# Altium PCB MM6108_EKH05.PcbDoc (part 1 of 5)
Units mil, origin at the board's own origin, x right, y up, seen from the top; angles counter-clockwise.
Board outline 6023.62 x 3425.2 mil, 4 copper layers (Top Layer, Ground Plane, Middle Layer, Bottom Layer), stack 76.15 mil thick; 212 components, 163 nets, 749 pads, 1477 vias.
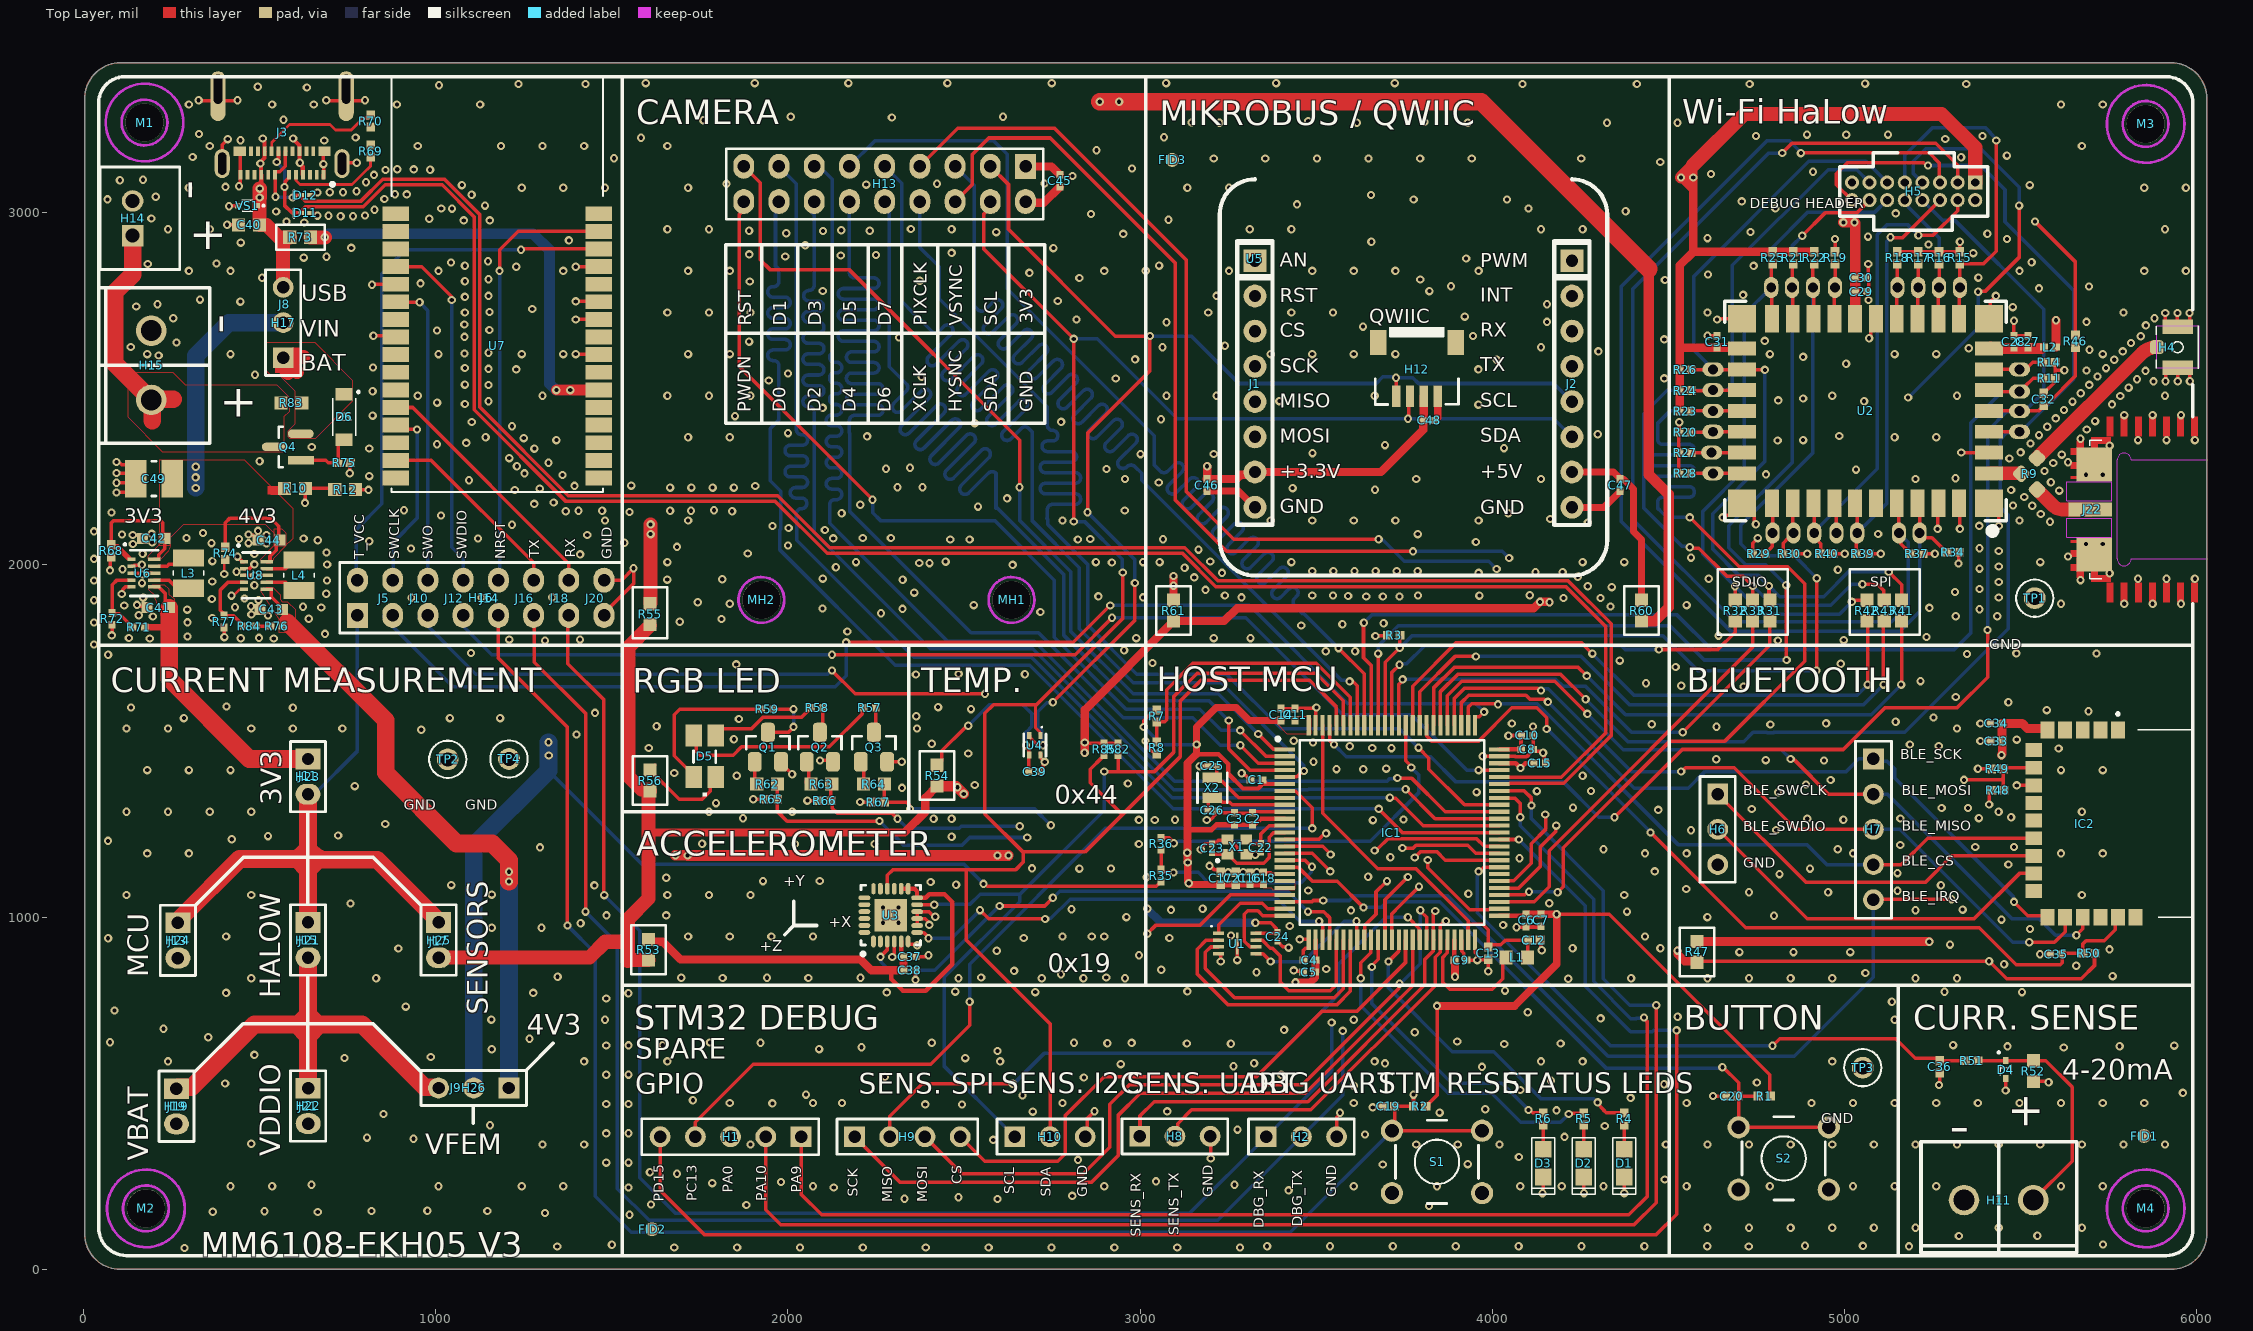
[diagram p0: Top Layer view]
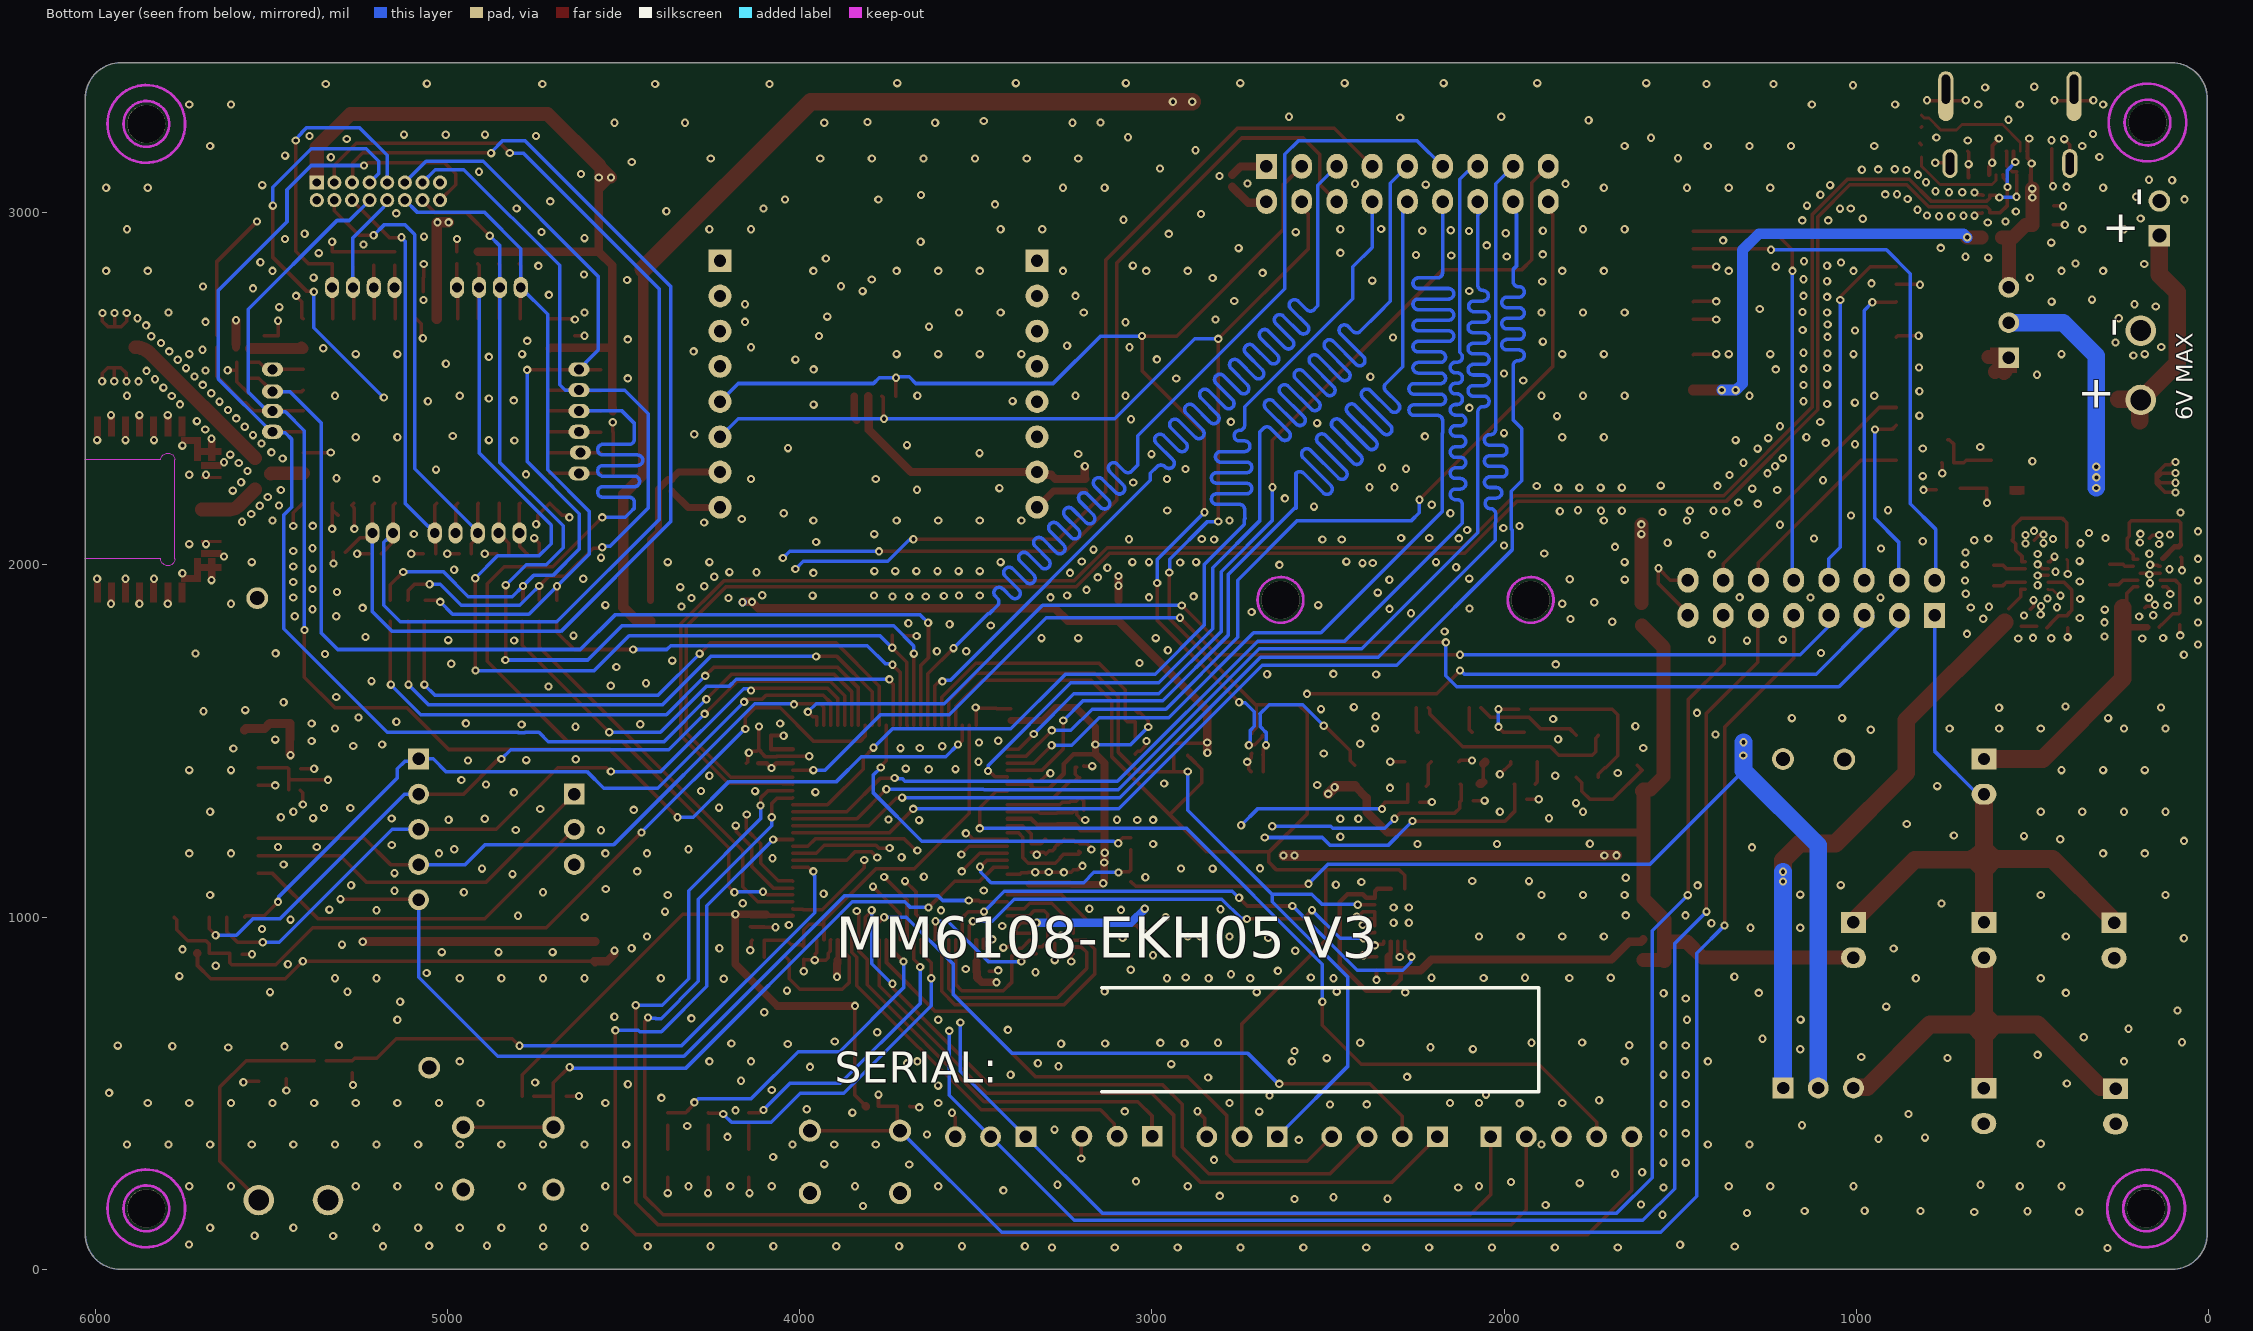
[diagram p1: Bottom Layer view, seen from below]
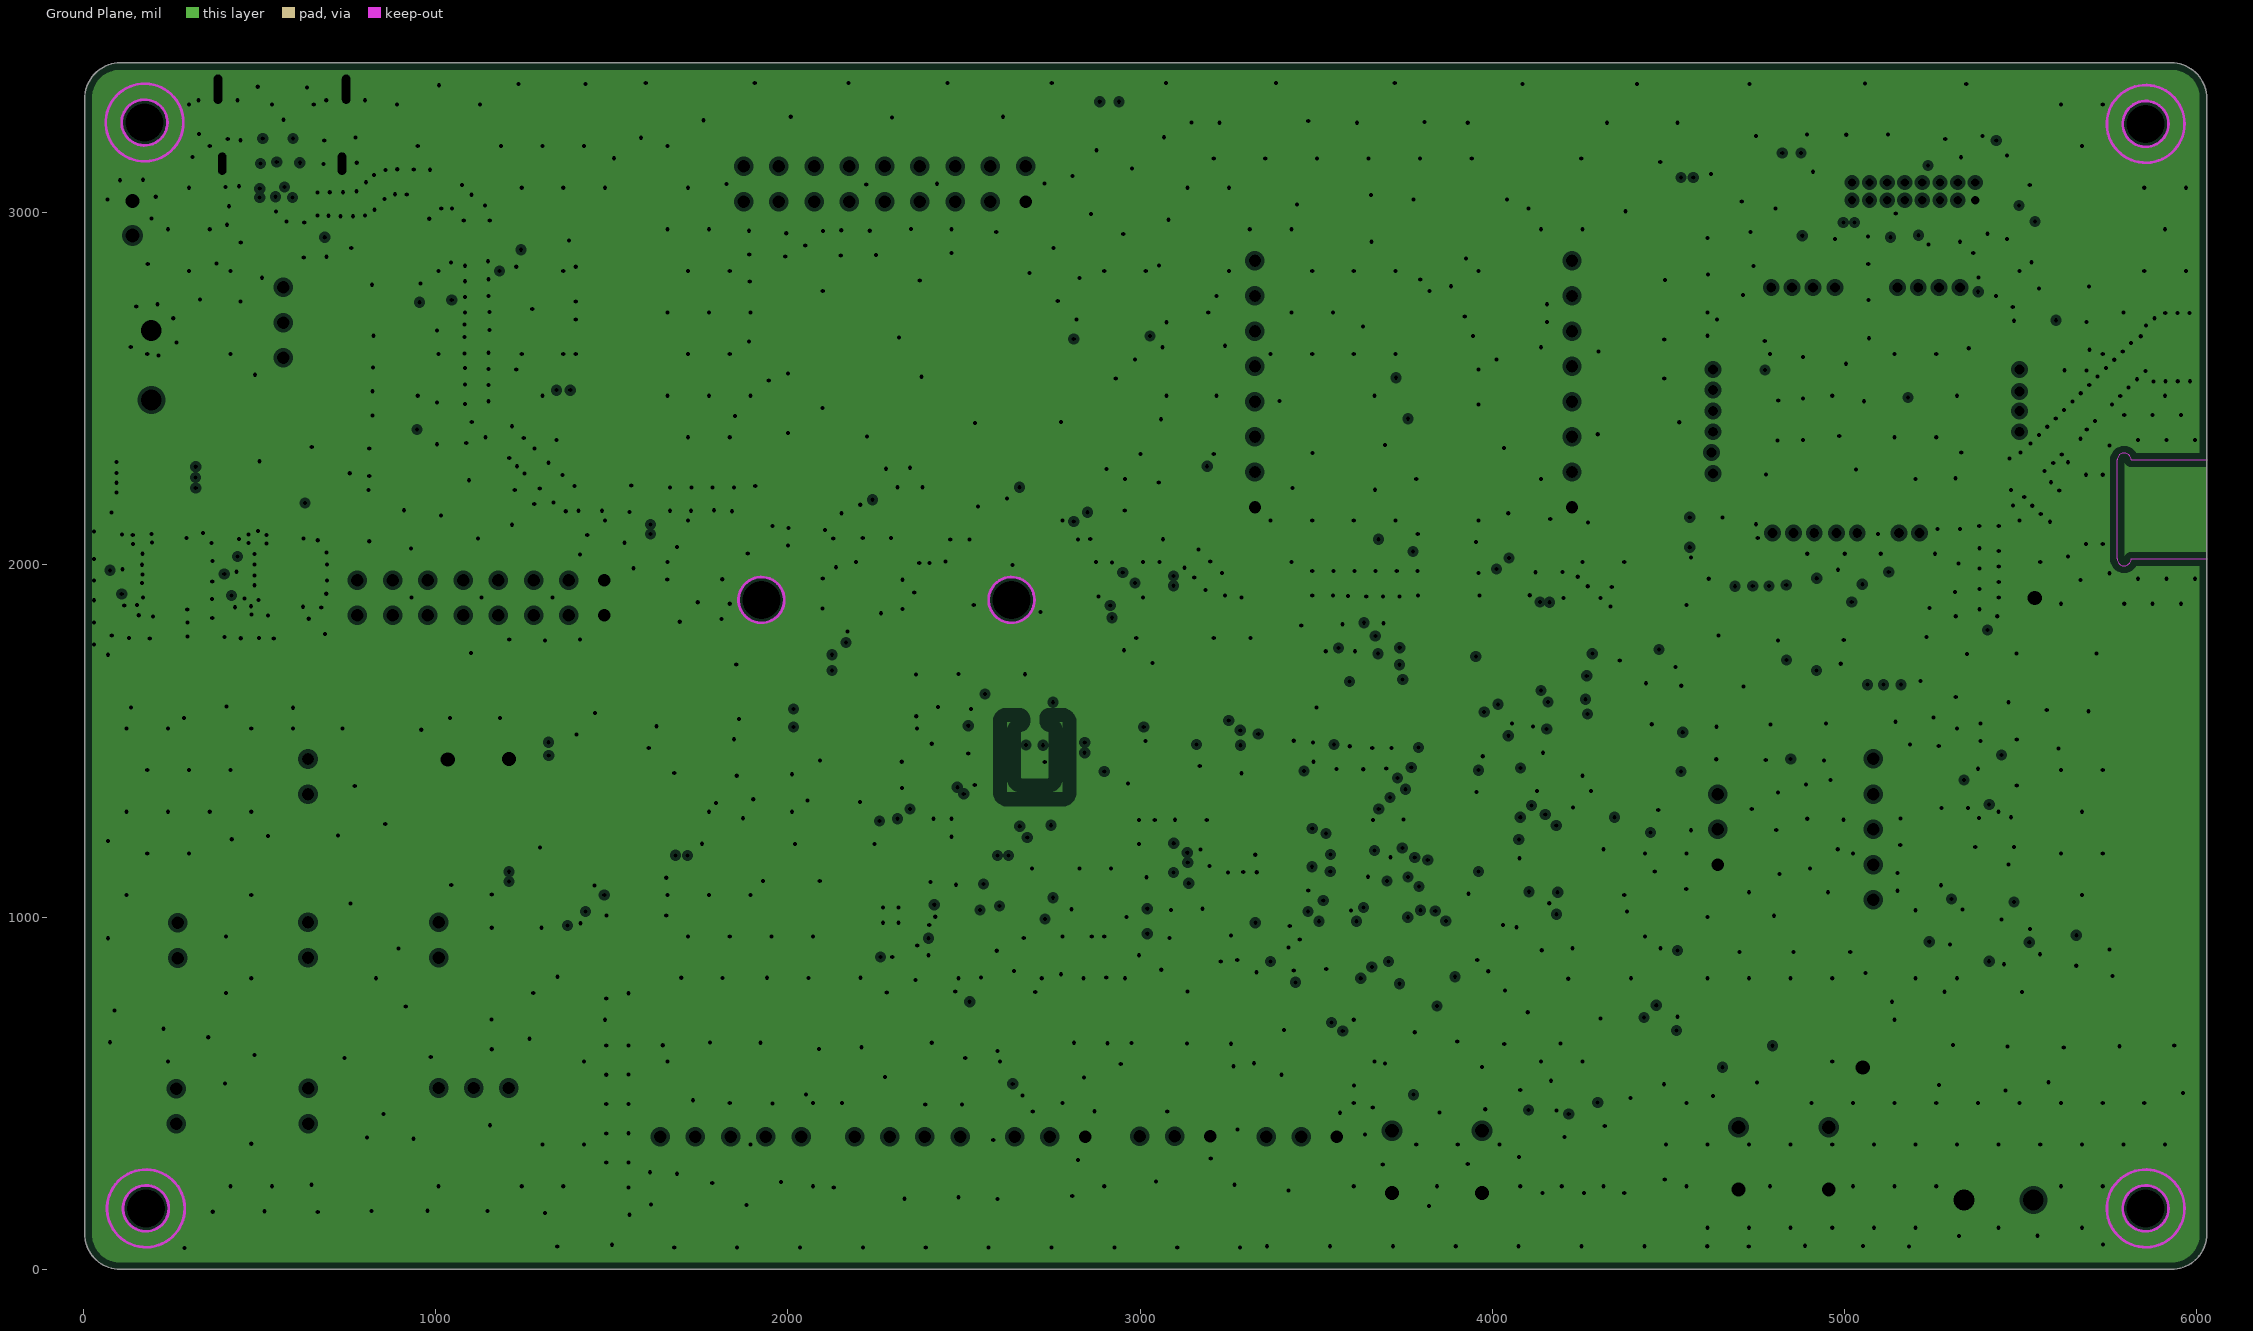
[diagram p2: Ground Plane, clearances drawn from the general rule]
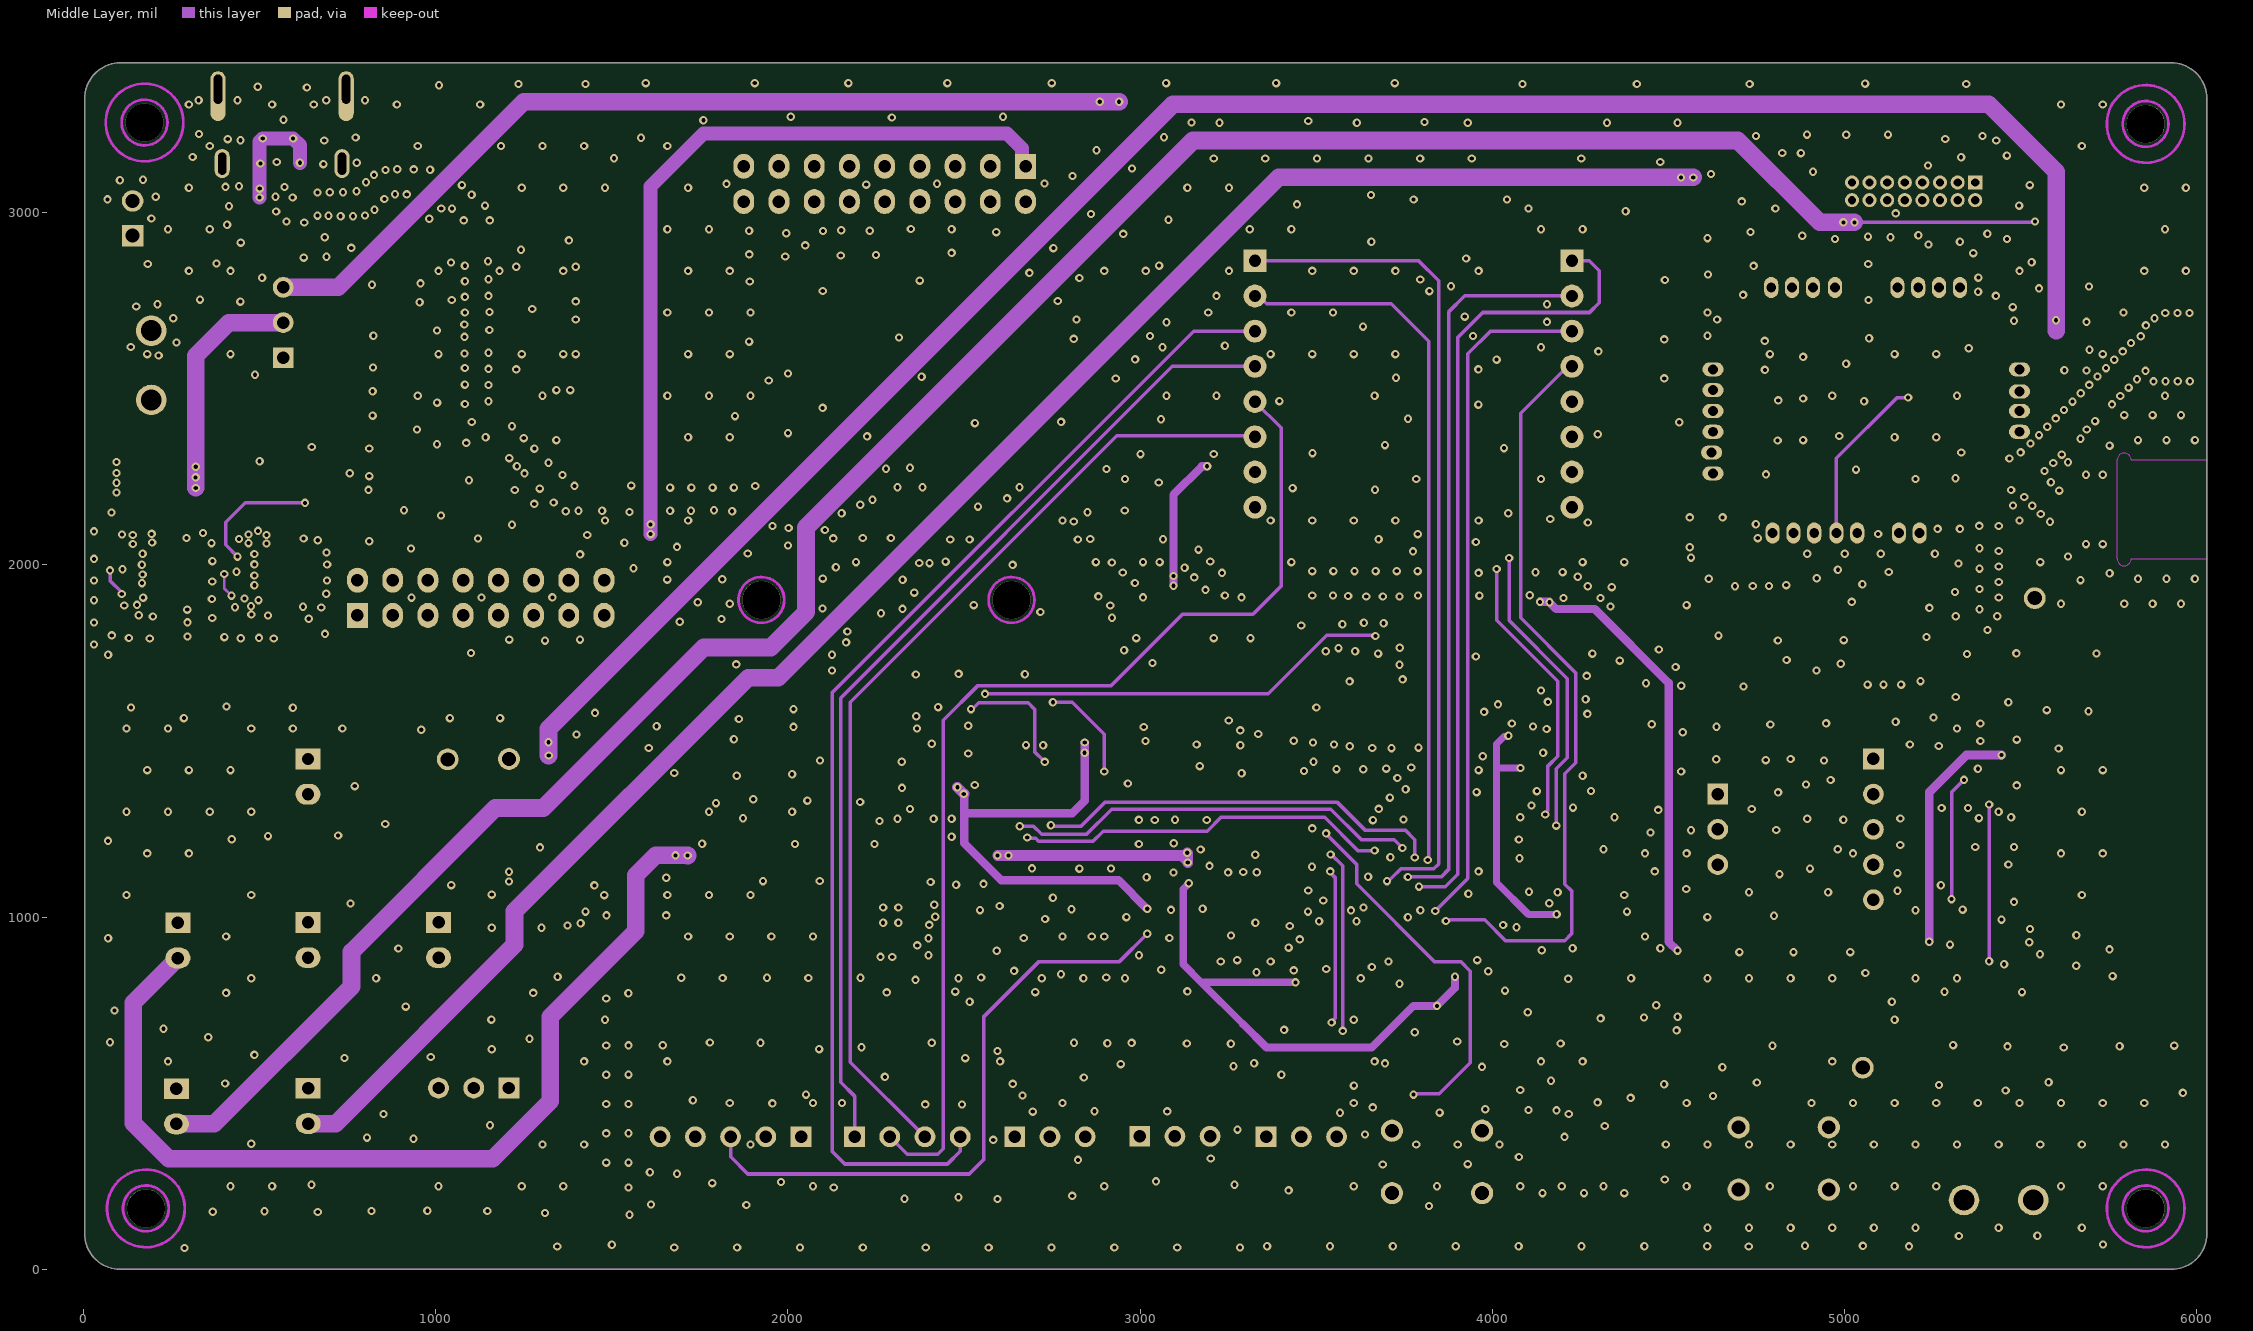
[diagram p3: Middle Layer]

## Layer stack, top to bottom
Top Solder: solder mask 0.8, SM-001, Dk 3.8
Top Layer: signal copper 1.4
Dielectric 2: prepreg 13.2, PP-006, Dk 4.11
Ground Plane: plane copper 1.25, net GND
Dielectric 1: prepreg 44.5, Core, Dk 4
Middle Layer: signal copper 1.25
Dielectric 5: prepreg 13.15, PP-006, Dk 4.11
Bottom Layer: signal copper 1.4
Bottom Solder: solder mask 0.8, SM-001, Dk 3.8

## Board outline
3.94,3188.98 3.94,3325.2 cw(c103.94,3325.2) 103.94,3425.2 5927.56,3425.2 cw(c5927.56,3325.2) 6027.56,3325.2 6027.56,100 cw(c5927.56,100) 5927.56,0 103.94,0 cw(c103.94,100) 3.94,100 3.94,275.59

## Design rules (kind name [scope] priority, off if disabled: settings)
AssemblyTestPointUsage [All] p0: scope1count=1 scope1_0_kind=Board scope1_0_value=Board scope2count=1 scope2_0_kind=Board scope2_0_value=Board commentlength=0
AssemblyTestPointUsage [All] p1: allowmultiple=TRUE
AssemblyTestpoint [All] p0: scope1count=1 scope1_0_kind=Board scope1_0_value=Board scope2count=1 scope2_0_kind=Board scope2_0_value=Board commentlength=0
AssemblyTestpoint [All] p1: testpointundercomponent=TRUE minsize=40 maxsize=100 preferedsize=60 minholesize=0 maxholesize=40 preferedholesize=32 testpointgrid=1 usegrid=FALSE gridtolerance=0.01 allowsidetop=TRUE
BoardOutlineClearance [All] p0 off: scope1count=1 scope1_0_kind=Board scope1_0_value=Board scope2count=1 scope2_0_kind=Board scope2_0_value=Board commentlength=140 gap=12 // Protel DXP Scope 1 Expression Was: (not OnTopSilkscreen) AND (NOT OnBottomSilkscreen) and (not OnMultiLayer) and (not InComponent('H3'))
BoardOutlineClearance [(not OnTopSilkscreen) AND (NOT OnBottomSilkscreen) and (not OnMultiLayer) and (not InComponent('H3'))] p1: gap=12 ignorepadtopadclearanceinfootprint=FALSE
Clearance Clearance_SMA [All] p0: scope1count=1 scope1_0_kind=Component scope1_0_value=J22 scope2count=1 scope2_0_kind=Component scope2_0_value=J22 commentlength=0 gap=0.01
Clearance Clearance_1 [All] p0: scope1count=1 scope1_0_kind=Board scope1_0_value=Board scope2count=1 scope2_0_kind=Board scope2_0_value=Board commentlength=0 gap=6
Clearance Clearance_USB [All] p0 off: scope1count=1 scope1_0_kind=Board scope1_0_value=Board scope2count=1 scope2_0_kind=Board scope2_0_value=Board commentlength=65 gap=6 // Protel DXP Scope 1 Expression Was: InDifferentialPair('USBC')
Clearance Clearance_RF [All] p0: scope1count=1 scope1_0_kind=NetClass scope1_0_value="50 Ohms" scope2count=1 scope2_0_kind=Board scope2_0_value=Board commentlength=0 gap=8.8
Clearance Clearance_RF_Poly [All] p0 off: scope1count=1 scope1_0_kind=Board scope1_0_value=Board scope2count=1 scope2_0_kind=NetClass scope2_0_value=RF-Net commentlength=50 gap=7.87 // Protel DXP Scope 1 Expression Was: (InPolygon)
Clearance Clearance_SMA [InComponent('J22') vs InComponent('J22')] p1: gap=0.01 ignorepadtopadclearanceinfootprint=TRUE
Clearance Clearance_RF_Poly [(InPolygon) vs InNetClass('RF-Net')] p2: gap=7.87 ignorepadtopadclearanceinfootprint=TRUE
Clearance Clearance_RF [InNetClass('50 Ohms')] p3: gap=8.8 ignorepadtopadclearanceinfootprint=TRUE except(3.94: Arc-Arc Arc-Track Track-Track)
Clearance Clearance_USB [InDifferentialPair('USBC')] p4: gap=6 ignorepadtopadclearanceinfootprint=TRUE
Clearance Clearance_1 [All] p5: gap=6 ignorepadtopadclearanceinfootprint=TRUE
ComponentClearance [All] p0: scope1count=1 scope1_0_kind=Board scope1_0_value=Board scope2count=1 scope2_0_kind=Board scope2_0_value=Board commentlength=0 gap=10 collisioncheckmode=3
DiffPairsRouting DiffPairsRouting_USBC [All] p0 off: scope1count=1 scope1_0_kind=Board scope1_0_value=Board scope2count=1 scope2_0_kind=Board scope2_0_value=Board commentlength=65 // Protel DXP Scope 1 Expression Was: InDifferentialPair('USBC')
DiffPairsRouting DiffPairsRouting_USBC [InDifferentialPair('USBC')] p1 off: maxlimit=10 minlimit=5 mostfreqgap=10 toplayer_maxgap=6 toplayer_prefgap=6 toplayer_minwidth=7.75 toplayer_maxwidth=11 toplayer_prefwidth=10 impedanceprofiledriven=TRUE impedanceprofileid={FA8D62EB-FDD2-4305-96CF-BF7F0CD6B75F} impedanceprofilevalue=90.000000 maxuncoupledlength=500
FabricationTestPointUsage [All] p0 off: scope1count=1 scope1_0_kind=Board scope1_0_value=Board scope2count=1 scope2_0_kind=Board scope2_0_value=Board commentlength=0 valid=0 allowmultiple=FALSE
FabricationTestPointUsage [All] p1 off: valid=0 allowmultiple=FALSE
FabricationTestpoint [All] p0 off: scope1count=1 scope1_0_kind=Board scope1_0_value=Board scope2count=1 scope2_0_kind=Board scope2_0_value=Board commentlength=63 side=1 testpointundercomponent=TRUE minsize=40 maxsize=100 preferedsize=60 minholesize=0 maxholesize=40 preferedholesize=32 testpointgrid=1 // Protel DXP Scope 1 Expression Was: (IsPad And OnMultiLayer)
FabricationTestpoint [(IsPad And OnMultiLayer)] p1 off: side=1 testpointundercomponent=TRUE minsize=40 maxsize=100 preferedsize=60 minholesize=0 maxholesize=40 preferedholesize=32 testpointgrid=1 allowsidetop=TRUE usegrid=TRUE gridtolerance=0.01
FanoutControl Fanout_Default [All] p0 off: scope1count=1 scope1_0_kind=Board scope1_0_value=Board scope2count=1 scope2_0_kind=Board scope2_0_value=Board commentlength=30 // Fanout_Default (Default Rule)
FanoutControl Fanout_Small [All] p0 off: scope1count=1 scope1_0_kind=Board scope1_0_value=Board scope2count=1 scope2_0_kind=Board scope2_0_value=Board commentlength=84 // Protel DXP Scope 1 Expression Was: (CompPinCount < 5)   Fanout_Small (Default Rule)
FanoutControl Fanout_SOIC [All] p0 off: scope1count=1 scope1_0_kind=Board scope1_0_value=Board scope2count=1 scope2_0_kind=Board scope2_0_value=Board commentlength=71 // Protel DXP Scope 1 Expression Was: IsSOIC   Fanout_SOIC (Default Rule)
FanoutControl Fanout_LCC [All] p0 off: scope1count=1 scope1_0_kind=Board scope1_0_value=Board scope2count=1 scope2_0_kind=Board scope2_0_value=Board commentlength=69 // Protel DXP Scope 1 Expression Was: IsLCC   Fanout_LCC (Default Rule)
FanoutControl Fanout_BGA [All] p0 off: scope1count=1 scope1_0_kind=Board scope1_0_value=Board scope2count=1 scope2_0_kind=Board scope2_0_value=Board commentlength=69 // Protel DXP Scope 1 Expression Was: IsBGA   Fanout_BGA (Default Rule)
FanoutControl Fanout_BGA [IsBGA] p1 off: bgadir=Out bgaviamode=Centered fanoutstyle=Auto fanoutdirection=Alternating viagrid=1 // Fanout_BGA (Default Rule)
FanoutControl Fanout_LCC [IsLCC] p2 off: bgadir=Out bgaviamode=Centered fanoutstyle=Auto fanoutdirection=Alternating viagrid=1 // Fanout_LCC (Default Rule)
FanoutControl Fanout_SOIC [IsSOIC] p3 off: bgadir=Out bgaviamode=Centered fanoutstyle=Auto fanoutdirection=Alternating viagrid=1 // Fanout_SOIC (Default Rule)
FanoutControl Fanout_Small [(CompPinCount < 5)] p4 off: bgadir=Out bgaviamode=Centered fanoutstyle=Auto fanoutdirection=OutThenIn viagrid=1 // Fanout_Small (Default Rule)
FanoutControl Fanout_Default [All] p5 off: bgadir=Out bgaviamode=Centered fanoutstyle=Auto fanoutdirection=Alternating viagrid=1 // Fanout_Default (Default Rule)
Height [All] p0 off: scope1count=1 scope1_0_kind=Board scope1_0_value=Board scope2count=1 scope2_0_kind=Board scope2_0_value=Board commentlength=0
Height "Under Socket" [All] p0 off: scope1count=1 scope1_0_kind=Board scope1_0_value=Board scope2count=1 scope2_0_kind=Board scope2_0_value=Board commentlength=64 // Protel DXP Scope 1 Expression Was: WithinRoom('ROOM_SOCKET')
Height "POGO Pins" [All] p0: scope1count=1 scope1_0_kind=ComponentClass scope1_0_value=POGO scope2count=1 scope2_0_kind=Board scope2_0_value=Board commentlength=0
Height TP1 [All] p0: scope1count=1 scope1_0_kind=Component scope1_0_value=TP1 scope2count=1 scope2_0_kind=Board scope2_0_value=Board commentlength=0
Height TP1 [InComponent('TP1')] p1: minheight=0 maxheight=472.44 prefheight=118.11
Height "POGO Pins" [InComponentClass('POGO')] p2: minheight=0 maxheight=275.59 prefheight=196.85
Height "Under Socket" [WithinRoom('ROOM_SOCKET')] p3: minheight=0 maxheight=157.48 prefheight=118.11
Height [All] p4 off: minheight=0 maxheight=1000 prefheight=500
HoleSize [All] p0: scope1count=1 scope1_0_kind=Board scope1_0_value=Board scope2count=1 scope2_0_kind=Board scope2_0_value=Board commentlength=0 absolutevalues=TRUE maxlimit=200 minlimit=6 maxpercent=80.000 minpercent=20.000
HoleSize [All] p1: absolutevalues=TRUE maxlimit=200 minlimit=6 maxpercent=80.000 minpercent=20.000
HoleToHoleClearance [All] p0: scope1count=1 scope1_0_kind=Board scope1_0_value=Board scope2count=1 scope2_0_kind=Board scope2_0_value=Board commentlength=0
HoleToHoleClearance [All] p1: gap=8 allowstackedmicrovias=TRUE
LayerPairs [All] p0 off: scope1count=1 scope1_0_kind=Board scope1_0_value=Board scope2count=1 scope2_0_kind=Board scope2_0_value=Board commentlength=0 enforce=TRUE
LayerPairs [All] p1 off: enforce=TRUE
MatchedLengths SDIO_2 [All] p0: scope1count=1 scope1_0_kind=NetClass scope1_0_value=SDIO_2 scope2count=1 scope2_0_kind=Board scope2_0_value=Board commentlength=0 tolerance=2000 amplitude=200 gap=20 style=90-Degree
MatchedLengths DCMI [All] p0: scope1count=1 scope1_0_kind=NetClass scope1_0_value=DCMI scope2count=1 scope2_0_kind=Board scope2_0_value=Board commentlength=0 tolerance=1000 amplitude=200 gap=20 style=90-Degree
MatchedLengths SDIO [All] p0: scope1count=1 scope1_0_kind=NetClass scope1_0_value=SDIO scope2count=1 scope2_0_kind=Board scope2_0_value=Board commentlength=0 tolerance=2000 amplitude=200 gap=20 style=90-Degree
MatchedLengths MatchLengths_U1_Passives_J5 [All] p0 off: scope1count=1 scope1_0_kind=Board scope1_0_value=Board scope2count=1 scope2_0_kind=Board scope2_0_value=Board commentlength=98 tolerance=50 amplitude=200 gap=20 style=90-Degree // Protel DXP Scope 1 Expression Was: InxSignalClass('xSignals_U1_Passives_J5_MatchLengthsClass')
MatchedLengths MatchLengths_U1_Passives_J5_1 [All] p0 off: scope1count=1 scope1_0_kind=Board scope1_0_value=Board scope2count=1 scope2_0_kind=Board scope2_0_value=Board commentlength=100 tolerance=50 amplitude=200 gap=20 style=90-Degree // Protel DXP Scope 1 Expression Was: InxSignalClass('xSignals_U1_Passives_J5_MatchLengthsClass_1')
MatchedLengths DCMI [InNetClass('DCMI')] p1: tolerance=1000 checknetsindiffpair=FALSE checkdiffpairvsdiffpair=TRUE checkxsignals=TRUE checkothers=TRUE
MatchedLengths SDIO [InNetClass('SDIO')] p2: tolerance=2000 checknetsindiffpair=FALSE checkdiffpairvsdiffpair=TRUE checkxsignals=TRUE checkothers=TRUE
MatchedLengths SDIO_2 [InNetClass('SDIO_2')] p3: tolerance=2000 checknetsindiffpair=FALSE checkdiffpairvsdiffpair=TRUE checkxsignals=TRUE checkothers=TRUE
MatchedLengths MatchLengths_U1_Passives_J5_1 [InxSignalClass('xSignals_U1_Passives_J5_MatchLengthsClass_1')] p4: tolerance=50 checknetsindiffpair=FALSE checkdiffpairvsdiffpair=TRUE checkxsignals=TRUE checkothers=TRUE
MatchedLengths MatchLengths_U1_Passives_J5 [InxSignalClass('xSignals_U1_Passives_J5_MatchLengthsClass')] p5: tolerance=50 checknetsindiffpair=FALSE checkdiffpairvsdiffpair=TRUE checkxsignals=TRUE checkothers=TRUE
MinimumSolderMaskSliver [All] p0 off: scope1count=1 scope1_0_kind=Board scope1_0_value=Board scope2count=1 scope2_0_kind=Board scope2_0_value=Board commentlength=96 // Protel DXP Scope 1 Expression Was: not InComponent('U4','U1','U5','U6','U7','U8','U9','U10')
MinimumSolderMaskSliver [not InComponent('U4','U1','U5','U6','U7','U8','U9','U10')] p1: minsoldermaskwidth=1
NetAntennae [All] p0: scope1count=1 scope1_0_kind=Board scope1_0_value=Board scope2count=1 scope2_0_kind=Board scope2_0_value=Board commentlength=0
PasteMaskExpansion [All] p0: scope1count=1 scope1_0_kind=Board scope1_0_value=Board scope2count=1 scope2_0_kind=Board scope2_0_value=Board commentlength=0 expansion=0
PlaneClearance [All] p0: scope1count=1 scope1_0_kind=Board scope1_0_value=Board scope2count=1 scope2_0_kind=Board scope2_0_value=Board commentlength=0 clearance=10
PlaneClearance [All] p1: clearance=10
PlaneConnect [All] p0: scope1count=1 scope1_0_kind=Board scope1_0_value=Board scope2count=1 scope2_0_kind=Board scope2_0_value=Board commentlength=0 planeconnectstyle=Relief reliefexpansion=20 reliefentries=4 reliefconductorwidth=10 reliefairgap=10
PlaneConnect PlaneConnect_1 [All] p0 off: scope1count=1 scope1_0_kind=Board scope1_0_value=Board scope2count=1 scope2_0_kind=Board scope2_0_value=Board commentlength=166 planeconnectstyle=Relief reliefexpansion=15.75 reliefentries=4 reliefconductorwidth=10 reliefairgap=7.87 // Protel DXP Scope 1 Expression Was: (InComponent('J5') OR InComponent('J6') OR InComponent('J13') OR InComponent('J11') OR InComponent('J12')) OR InComponent('H3')
PlaneConnect PlaneConnect_1 [(InComponent('J5') OR InComponent('J6') OR InComponent('J13') OR InComponent('J11') OR InComponent('J12')) OR InComponent('H3')] p1: planeconnectstyle=Relief reliefexpansion=15.75 reliefentries=4 reliefconductorwidth=10 reliefairgap=7.87
PlaneConnect [All] p2: pad.planeconnectstyle=Relief pad.reliefexpansion=20 pad.reliefentries=4 pad.reliefconductorwidth=10 pad.reliefairgap=10 via.planeconnectstyle=Direct via.reliefexpansion=20 via.reliefentries=4 via.reliefconductorwidth=10 via.reliefairgap=10
PolygonConnect [All] p0: scope1count=1 scope1_0_kind=Board scope1_0_value=Board scope2count=1 scope2_0_kind=Board scope2_0_value=Board commentlength=0 connectstyle=Relief reliefconductorwidth=10 reliefentries=4 polygonreliefangle="90 Angle"
PolygonConnect PolygonConnect_1 [All] p0 off: scope1count=1 scope1_0_kind=Net scope1_0_value=GND scope2count=1 scope2_0_kind=Board scope2_0_value=Board commentlength=145 connectstyle=Relief reliefconductorwidth=10 reliefentries=4 polygonreliefangle="90 Angle" // Protel DXP Scope 2 Expression Was: (InComponent('J5') OR InComponent('J6') OR InComponent('J13') OR InComponent('J11') OR InComponent('J12'))
PolygonConnect PolygonConnect_1 [InNet('GND') vs (InComponent('J5') OR InComponent('J6') OR InComponent('J13') OR InComponent('J11') OR InComponent('J12'))] p1: connectstyle=Relief reliefconductorwidth=10 reliefentries=4 polygonreliefangle="90 Angle" airgapwidth=7.87
PolygonConnect [All] p2: thpad.connectstyle=Relief thpad.reliefconductorwidth=10 thpad.reliefentries=4 thpad.polygonreliefangle="90 Angle" thpad.airgapwidth=10 smdpad.connectstyle=Direct smdpad.reliefconductorwidth=10 smdpad.reliefentries=4 smdpad.polygonreliefangle="90 Angle" smdpad.airgapwidth=10 via.connectstyle=Direct via.reliefconductorwidth=10 via.reliefentries=4 via.polygonreliefangle="90 Angle" via.airgapwidth=10
RoutingCorners [All] p0: scope1count=1 scope1_0_kind=Board scope1_0_value=Board scope2count=1 scope2_0_kind=Board scope2_0_value=Board commentlength=0 cornerstyle=45-Degree minsetback=100 maxsetback=100
RoutingLayers [All] p0: scope1count=1 scope1_0_kind=Board scope1_0_value=Board scope2count=1 scope2_0_kind=Board scope2_0_value=Board commentlength=0 top layer=Automatic mid layer 1=Automatic bottom layer=Automatic
RoutingPriority [All] p0: scope1count=1 scope1_0_kind=Board scope1_0_value=Board scope2count=1 scope2_0_kind=Board scope2_0_value=Board commentlength=0
RoutingTopology [All] p0: scope1count=1 scope1_0_kind=Board scope1_0_value=Board scope2count=1 scope2_0_kind=Board scope2_0_value=Board commentlength=0 topology=Shortest
RoutingVias [All] p0: scope1count=1 scope1_0_kind=Board scope1_0_value=Board scope2count=1 scope2_0_kind=Board scope2_0_value=Board commentlength=0 holewidth=11.81 width=23.62 viastyle="Through Hole" minholewidth=8 minwidth=19.68 maxholewidth=28 maxwidth=50
RoutingVias [All] p1: holewidth=11.81 width=23.62 viastyle="Through Hole" minholewidth=8 minwidth=19.68 maxholewidth=28 maxwidth=50
ShortCircuit [All] p0: scope1count=1 scope1_0_kind=Board scope1_0_value=Board scope2count=1 scope2_0_kind=Board scope2_0_value=Board commentlength=0 allowed=FALSE
SilkToBoardRegionClearance [All] p0: scope1count=1 scope1_0_kind=Board scope1_0_value=Board scope2count=1 scope2_0_kind=Board scope2_0_value=Board commentlength=0
SilkToSilkClearance [All] p0: scope1count=1 scope1_0_kind=Board scope1_0_value=Board scope2count=1 scope2_0_kind=Board scope2_0_value=Board commentlength=0
SilkToSilkClearance [All] p1: silktosilkclearance=8
SilkToSolderMaskClearance [All] p0 off: scope1count=1 scope1_0_kind=Board scope1_0_value=Board scope2count=1 scope2_0_kind=Board scope2_0_value=Board commentlength=44 // Protel DXP Scope 1 Expression Was: IsPad
SilkToSolderMaskClearance [IsPad] p1: minsilkscreentomaskgap=4 clearancetoexposedcopper=TRUE
SolderMaskExpansion [All] p0: scope1count=1 scope1_0_kind=Board scope1_0_value=Board scope2count=1 scope2_0_kind=Board scope2_0_value=Board commentlength=0 expansion=4
SolderMaskExpansion [All] p1: expansion=4 istentingtop=FALSE
SupplyNets [All] p0: scope1count=1 scope1_0_kind=Net scope1_0_value=GND scope2count=1 scope2_0_kind=Board scope2_0_value=Board commentlength=0 voltage=0.000
SupplyNets SupplyNets_7 [All] p0: scope1count=1 scope1_0_kind=Net scope1_0_value=VDD_PA scope2count=1 scope2_0_kind=Board scope2_0_value=Board commentlength=0 voltage=4.000
SupplyNets SupplyNets_6 [All] p0: scope1count=1 scope1_0_kind=Net scope1_0_value=VDD_LNA scope2count=1 scope2_0_kind=Board scope2_0_value=Board commentlength=0 voltage=4.000
SupplyNets SupplyNets_5 [All] p0: scope1count=1 scope1_0_kind=Net scope1_0_value=VDD_FEM scope2count=1 scope2_0_kind=Board scope2_0_value=Board commentlength=0 voltage=4.000
SupplyNets SupplyNets_4 [All] p0: scope1count=1 scope1_0_kind=Net scope1_0_value=VDD5_RPi scope2count=1 scope2_0_kind=Board scope2_0_value=Board commentlength=0 voltage=5.000
SupplyNets SupplyNets_3 [All] p0: scope1count=1 scope1_0_kind=Net scope1_0_value=VDD5 scope2count=1 scope2_0_kind=Board scope2_0_value=Board commentlength=0 voltage=5.000
SupplyNets SupplyNets_2 [All] p0: scope1count=1 scope1_0_kind=Net scope1_0_value=VBAT scope2count=1 scope2_0_kind=Board scope2_0_value=Board commentlength=0 voltage=3.300
SupplyNets SupplyNets_1 [All] p0: scope1count=1 scope1_0_kind=Net scope1_0_value=VDD33 scope2count=1 scope2_0_kind=Board scope2_0_value=Board commentlength=0 voltage=3.300
SupplyNets SupplyNets_1 [InNet('VDD33')] p1: voltage=3.300
SupplyNets SupplyNets_2 [InNet('VBAT')] p2: voltage=3.300
SupplyNets SupplyNets_3 [InNet('VDD5')] p3: voltage=5.000
SupplyNets SupplyNets_4 [InNet('VDD5_RPi')] p4: voltage=5.000
SupplyNets SupplyNets_5 [InNet('VDD_FEM')] p5: voltage=4.000
SupplyNets SupplyNets_6 [InNet('VDD_LNA')] p6: voltage=4.000
SupplyNets SupplyNets_7 [InNet('VDD_PA')] p7: voltage=4.000
SupplyNets [InNet('GND')] p8: voltage=0.000
UnConnectedPin [All] p0 off: scope1count=1 scope1_0_kind=Board scope1_0_value=Board scope2count=1 scope2_0_kind=Board scope2_0_value=Board commentlength=0
UnConnectedPin [All] p1 off:
UnRoutedNet [All] p0: scope1count=1 scope1_0_kind=Board scope1_0_value=Board scope2count=1 scope2_0_kind=Board scope2_0_value=Board commentlength=0
UnRoutedNet [All] p1: checkbadconnections=TRUE
UnpouredPolygon [All] p0: scope1count=1 scope1_0_kind=Board scope1_0_value=Board scope2count=1 scope2_0_kind=Board scope2_0_value=Board commentlength=0
Width "RF Width_1" [All] p0 off: scope1count=1 scope1_0_kind=Board scope1_0_value=Board scope2count=1 scope2_0_kind=Board scope2_0_value=Board commentlength=65 maxlimit=23.62 minlimit=4.18 preferedwidth=10 // Protel DXP Scope 1 Expression Was: InDifferentialPair('USBC')
Width [All] p0: scope1count=1 scope1_0_kind=Board scope1_0_value=Board scope2count=1 scope2_0_kind=Board scope2_0_value=Board commentlength=0 maxlimit=50 minlimit=8 preferedwidth=8
Width "RF Width" [All] p0: scope1count=1 scope1_0_kind=NetClass scope1_0_value="50 OHMs" scope2count=1 scope2_0_kind=Board scope2_0_value=Board commentlength=0 maxlimit=39.37 minlimit=4.18 preferedwidth=10
Width "RF Width" [InNetClass('50 OHMs')] p1: maxlimit=39.37 minlimit=4.18 preferedwidth=10 toplayer_minwidth=12.51 toplayer_prefwidth=39 impedanceprofiledriven=TRUE impedanceprofileid={FF55CEB2-EE64-462C-BC0D-290E837BE369} impedanceprofilevalue=50.000000 minimp=50.000000 maximp=50.000000 favimp=50.000000
Width "RF Width_1" [InDifferentialPair('USBC')] p2: maxlimit=23.62 minlimit=4.18 preferedwidth=10 toplayer_minwidth=7 minimp=50.000000 maximp=50.000000 favimp=50.000000
Width [All] p3: maxlimit=50 minlimit=8 preferedwidth=8
10 further rules are at their usual default settings.

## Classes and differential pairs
component class U_Mechanical: FID1 FID2 FID3 J5 J8 J9 J10 J11 J12 J13 J14 J15 J16 J17 J18 J19 J20 J21 M1 M2 M3 M4 TP1 TP2 TP3 TP4
net class SDIO_2: SDMMC2_CLK SDMMC2_CMD SDMMC2_D0
net class DCMI: CAM_XCLK DCMI_D0 DCMI_D1 DCMI_D2 DCMI_D3 DCMI_D4 DCMI_D5 DCMI_D6 DCMI_D7 DCMI_HSYNC DCMI_PIXCLK DCMI_VSYNC
net class SDIO: MM_SDIO_CLK MM_SDIO_CMD MM_SDIO_D0 MM_SDIO_D1 MM_SDIO_D2 MM_SDIO_D3
net class "50 OHMs": ANT NetH4_1 NetJ22_1
component class U_Sensors: C36 C37 C38 C39 C45 C46 C47 C48 D4 D5 H8 H9 H10 H11 H12 H13 J1 J2 MH1 MH2 Q1 Q2 Q3 R51 R52 R53 R54 R55 R56 R57 R58 R59 R60 R61 R62 R63 R64 R65 R66 R67 U3 U4 U5
component class U_Power: C40 C41 C42 C43 C44 C49 D6 D11 D12 H14 H15 H16 H17 H19 H21 H22 H23 H24 H25 H26 J3 L3 L4 Q4 R10 R12 R35 R36 R68 R69 R70 R71 R72 R73 R74 R75 R76 R77 R83 R84 U6 U7 U8 VS1
component class U_BLE_Module: C33 C34 C35 H6 H7 IC2 R47 R48 R49 R50
component class U_STM_MCU: C1 C2 C3 C4 C5 C6 C7 C8 C9 C10 C11 C12 C13 C14 C15 C16 C17 C18 C19 C20 C21 C22 C23 C24 C25 C26 D1 D2 D3 H1 H2 IC1 L1 R1 R2 R3 R4 R5 R6 R7 R8 R82 R85 S1 S2 U1 X1 X2
component class U_HaLow_Module: C27 C28 C29 C30 C31 C32 H4 H5 J22 L2 R9 R11 R14 R15 R16 R17 R18 R19 R20 R21 R22 R23 R24 R25 R26 R27 R28 R29 R30 R31 R32 R33 R34 R37 R39 R40 R41 R42 R43 R46 U2
differential pair " ": +USBC_P -USBC_N

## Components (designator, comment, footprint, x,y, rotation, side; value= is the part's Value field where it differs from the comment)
C1 "GRM155R61A475MEAAD" 0402_cap 3330,1390 r0 top
C2 "C1005X7R1H104K050BE" 0402_cap 3318.9,1279.53 r270 top
C3 "CL05A106MP8NUB8" 0402_cap 3267.72,1279.53 r270 top
C4 "C1005X7R1H104K050BE" 0402_cap 3480.31,877.95 r0 top
C5 "CL05A106MP8NUB8" 0402_cap 3479.02,844.11 r0 top
C6 "C1005X7R1H104K050BE" 0402_cap 4095.37,990.6 r90 top
C7 "CL05A106MP8NUB8" 0402_cap 4137.08,991.19 r90 top
C8 "C1005X7R1H104K050BE" 0402_cap 4098.43,1476.38 r180 top
C9 "CL05A106MP8NUB8" 0402_cap 3909.45,877.95 r0 top
C10 "CL05A106MP8NUB8" 0402_cap 4098.43,1515.75 r180 top
C11 "C1005X7R1H104K050BE" 0402_cap 3440,1575 r270 top
C12 "GRM155R61E225ME15D" CAPC1005X06N 4117.13,935.04 r0 top
C13 "GRM155R61E225ME15D" CAPC1005X06N 3988.19,897.64 r270 top
C14 "CL05A106MP8NUB8" 0402_cap 3400,1575 r270 top
C15 "C1005X7R1H104K050BE" 0402_cap 4133.86,1437.01 r180 top
C16 "C1005X7R1H104K050BE" 0402_cap 3311.02,1110.24 r270 top
C17 "CL05A105KA5NQNC" CAPC1005X06N 3228.35,1110.24 r270 top
C18 "C1005X7R1H104K050BE" 0402_cap 3350.39,1110.24 r270 top
C19 "LMK105BJ104KV-F" CAPC1005X06N 3704.72,462.6 r180 top
C20 "LMK105BJ104KV-F" CAPC1005X06N 4679.13,492.13 r180 top
C21 "CL05A105KA5NQNC" CAPC1005X06N 3271.65,1110.24 r270 top
C22 "GRM0335C1E120JA01D" CAPC0603X03N 3342.52,1196.85 r270 top
C23 "GRM0335C1E120JA01D" CAPC0603X03N 3203.74,1195.87 r90 top
C24 "CL03A104KQ3NNNC" CAPC0603X03N 3389.76,944.88 r90 top
C25 "GRM0335C1E120JA01D" CAPC0603X03N 3204.72,1429.13 r0 top
C26 "GRM0335C1E120JA01D" CAPC0603X03N 3204.72,1303.15 r180 top
C27 "CL05A106MP8NUB8" 0402_cap 5519.69,2633.86 r90 top
C28 "C1005X7R1H104K050BE" 0402_cap 5480.31,2633.86 r90 top
C29 "C1005X7R1H104K050BE" 0402_cap 5046.18,2775.59 r0 top
C30 "CL05A106MP8NUB8" 0402_cap 5046.18,2814.96 r0 top
C31 "C1005X7R1H104K050BE" 0402_cap 4637.8,2633.86 r90 top
C32 "GRM155R61E225ME15D" CAPC1005X06N 5565,2470 r90 top
C33 "GRM155R61E225ME15D" CAPC1005X06N 5430,1500 r180 top
C34 "C1005X7R1H104K050BE" 0402_cap 5430,1550 r0 top
C35 "GRM155R71E103KA01D" 0402_cap 5600,895 r0 top
C36 "GRM155R71E103KA01D" CAPC1005X06N 5269.69,575.2 r270 top
C37 "C1005X7R1H104K050BE" 0402_cap 2345,888 r180 top
C38 "CL05A106MP8NUB8" 0402_cap 2345,849 r180 top
C39 "C1005X7R1H104K050BE" 0402_cap 2700.79,1413.39 r180 top
C40 "GRM188R61E106MA73J" CAPC1608X06N 470,2965 r180 top
C41 "GRM188R60J226MEA0D" 0603_cap 211.96,1878.74 r0 top
C42 "GRM188R60J106ME84D" 0603_cap 199.37,2075.12 r0 top
C43 "GRM188R60J226MEA0D" 0603_cap 533.15,1873.47 r0 top
C44 "GRM188R60J106ME84D" 0603_cap 526.34,2070.32 r0 top
C45 "C1005X7R1H104K050BE" 0402_cap 2771.65,3090.55 r90 top
C46 "C1005X7R1H104K050BE" 0402_cap 3188.98,2226.77 r90 top
C47 "C1005X7R1H104K050BE" 0402_cap 4362.2,2226.77 r90 top
C48 "C1005X7R1H104K050BE" 0402_cap 3820,2410 r180 top
C49 "CL32A107MPVNNNE" CAPC3225X20N 200,2245 r180 top
D1 "LTST-C170KRKT" LED_0805_RED 4374.02,301.57 r270 top
D2 "LTST-C170KGKT" LED_0805_GREEN 4258.86,301.57 r270 top
D3 "LTST-C170TBKT" LED_0805_BLUE 4143.7,301.57 r270 top
D4 "ESD8351XV2T1G" SOD-523-DIODE 5456.69,566.93 r270 top
D5 "150120M173000" WL-SFCW_1206 1763.78,1456.69 r90 top
D6 "MMSZ5231B7F" SOD-123FL 740,2420 r270 top
D11 "ESDALC6V1-1U2" 0201_DIODE 630,2999.22 r0 top
D12 "ESDALC6V1-1U2" 0201_DIODE 630,3050 r0 top
FID1 "PAD0002" FIDUCIAL_1MM 5849.65,378.7 r90 top
FID2 "PAD0002" FIDUCIAL_1MM 1614,114 r90 top
FID3 "PAD0002" FIDUCIAL_1MM 3090.55,3149.61 r90 top
H1 "2011-1X05G00SB" "HDR1X5 - Short Gold" 1887.01,376.69 r180 top
H2 "2011-1X03G00SB" HDR1X3 3457.38,376.69 r0 top
H4 "U.FL-R-SMT" U_FL-R-SMT 5944.88,2618.11 r270 top
H5 "FTSH-108-01-F-D-K" FTSH_108_D_K 5195.47,3060.43 r180 top
H6 "2011-1X03G00SB" HDR1X3 4639.37,1249.29 r270 top
H7 "2011-1X05G00SB" "HDR1X5 - Short Gold" 5081.42,1299.29 r270 top
H8 "2011-1X03G00SB" HDR1X3 3098.43,377.95 r0 top
H9 "2011-1X04G00SB" "HDR1X4 - Short Gold" 2338.88,376.69 r0 top
H10 "2011-1X03G00SB" HDR1X3 2743.7,376.69 r0 top
H11 "OSTTC020162" SCREW_TERM_2WAY_5MM 5338.58,196.85 r0 top
H12 "SM04B-SRSS-TBLFSN" SM04B-SRSS-TB 3785.59,2555.28 r90 top
H13 "PPTC092LFBN-RC" "HDR2X9 Female" 2674.41,3131.5 r180 top
H14 "B2B-XH-A" B2B-XH-A 160.12,2984.09 r90 top
H15 "OSTTC020162" SCREW_TERM_2WAY_5MM 192.6,2665.04 r270 top
H16 "2011-2X08TSB" "HDR2X8 Short Gold" 1077.76,1906.69 r0 top
H17 "2011-1X03G00SB" HDR1X3 566.93,2687.87 r90 top
H19 "2011-1X02G00SB-1" HDR1X2 264,463 r270 top
H21 "2011-1X02G00SB-1" HDR1X2 637.35,935 r270 top
H22 "2011-1X02G00SB-1" HDR1X2 638,464 r270 top
H23 "2011-1X02G00SB-1" HDR1X2 637.35,1399 r270 top
H24 "2011-1X02G00SB-1" HDR1X2 268,934 r270 top
H25 "2011-1X02G00SB-1" HDR1X2 1008,935 r270 top
H26 "2011-1X03G00SB" HDR1X3 1107.88,515 r180 top
IC1 "STM32U585VIT6Q" STM32U585VIT6 3714.57,1240.16 r0 top locked
IC2 "BLUENRG-M2SP" BLUENRGM2SP 5725.59,1265.75 r270 top
J1 "75915-308GLF" 75915-308LF 3325.59,2863.58 r0 top
J2 "75915-308GLF" 75915-308LF 4225.59,2863.58 r0 top
J3 "2012670005" USB-C_RCP 563.78,3228.94 r180 top locked
J5 "QPC02SXGN-RC" FP-QPC02SXGN-RC-MFG 852.76,1905.51 r90 top
J8 "QPC02SXGN-RC" FP-QPC02SXGN-RC-MFG 570,2740 r90 top
J9 "QPC02SXGN-RC" FP-QPC02SXGN-RC-MFG 1056.49,515 r180 top
J10 "QPC02SXGN-RC" FP-QPC02SXGN-RC-MFG 952.76,1905.51 r90 top
J11 "QPC02SXGN-RC" FP-QPC02SXGN-RC-MFG 638.16,1401.43 r90 top
J12 "QPC02SXGN-RC" FP-QPC02SXGN-RC-MFG 1052.76,1905.51 r90 top
J13 "QPC02SXGN-RC" FP-QPC02SXGN-RC-MFG 267.04,933.35 r90 top
J14 "QPC02SXGN-RC" FP-QPC02SXGN-RC-MFG 1152.76,1905.51 r90 top
J15 "QPC02SXGN-RC" FP-QPC02SXGN-RC-MFG 638.16,934.43 r90 top
J16 "QPC02SXGN-RC" FP-QPC02SXGN-RC-MFG 1252.76,1905.51 r90 top
J17 "QPC02SXGN-RC" FP-QPC02SXGN-RC-MFG 1009,932 r90 top
J18 "QPC02SXGN-RC" FP-QPC02SXGN-RC-MFG 1352.76,1905.51 r90 top
J19 "QPC02SXGN-RC" FP-QPC02SXGN-RC-MFG 265,463 r270 top
J20 "QPC02SXGN-RC" FP-QPC02SXGN-RC-MFG 1452.76,1905.51 r90 top
J21 "QPC02SXGN-RC" FP-QPC02SXGN-RC-MFG 638.16,462.78 r90 top
J22 "SM2924" SM2924-Footprint-1 5984.25,2157.48 r180 top
L1 "ASMPH-0603-2R2M-T" INDC1608X10N 4068.9,885.83 r180 top
L2 "BLM15PX600SN1D" 0402_ind 5582.68,2618.11 r0 top
L3 "DFE252012PR47MP2" INDC2520X120N 297.8,1976.69 r270 top
L4 "DFE252012PR47MP2" INDC2520X120N 611.55,1970.58 r270 top
M1 "MH_300_275_NPTH" MH_300_275_NPTH 173.23,3255.91 r0 top
M2 "MH_300_275_NPTH" MH_300_275_NPTH 177.17,173.23 r0 top
M3 "MH_300_275_NPTH" MH_300_275_NPTH 5854.33,3251.97 r0 top
M4 "MH_300_275_NPTH" MH_300_275_NPTH 5854.33,173.23 r0 top
MH1 "PAD0009" MH_300_275_NPTH 2634.57,1900.63 r0 top
MH2 "PAD0009" MH_300_275_NPTH 1924.57,1900.63 r0 top
Q1 "2N7002NXAKR" SOT95P240X120_GSD-3N(SOT23-3L) 1942.91,1484.25 r0 top
Q2 "2N7002NXAKR" SOT95P240X120_GSD-3N(SOT23-3L) 2090.54,1484.25 r0 top
Q3 "2N7002NXAKR" SOT95P240X120_GSD-3N(SOT23-3L) 2244.09,1484.25 r0 top
Q4 "IRLML6401TRPBF" FP-SOT23-IPC_A 580,2335 r180 top
R1 "MCR01MZPF1002" RESC1005X04N 4771.65,492.13 r180 top
R2 "MCR01MZPF1002" RESC1005X04N 3793.31,462.6 r180 top
R3 "ERJ-2RKF1001X" RESC1005X04N 3720,1800 r0 top
R4 "ERJ-2RKF1001X" RESC1005X04N 4374.02,427.16 r270 top
R5 "ERJ-2RKF1001X" RESC1005X04N 4258.86,427.16 r270 top
R6 "ERJ-2RKF1001X" RESC1005X04N 4143.7,427.16 r270 top
R7 "MCR01MZPF1002" RESC1005X04N 3047.24,1570.87 r90 top
R8 "MCR01MZPF1002" RESC1005X04N 3047.24,1480.31 r270 top
R9 "RES_AB" 0603_RES_AB_RA 5523.62,2236.22 r315 top
R10 "RC0603JR-070RL" RESC1608X06N 600.48,2217.17 r180 top
R11 "ERJ-2RKF1002X" RESC1005X04N 5580,2530 r180 top
R12 "RC0603JR-070RL" RESC1608X06N 743,2214 r0 top
R14 "ERJ-2RKF1002X" RESC1005X04N 5580,2575 r180 top
R15 "ERJ-2RKF1002X" RESC1005X04N 5326.77,2871.65 r270 top
R16 "ERJ-2RKF1002X" RESC1005X04N 5267.72,2871.65 r270 top
R17 "ERJ-2RKF1002X" RESC1005X04N 5208.66,2871.65 r270 top
R18 "ERJ-2RKF1002X" RESC1005X04N 5149.61,2871.65 r270 top
R19 "ERJ-2RKF1002X" RESC1005X04N 4972.44,2871.65 r270 top
R20 "ERJ-2RKF1002X" RESC1005X04N 4546.6,2376.97 r0 top
R21 "MCR01MZPF4702" RESC1005X04N 4854.33,2871.65 r270 top
R22 "MCR01MZPF4702" RESC1005X04N 4913.39,2871.65 r270 top
R23 "MCR01MZPF4702" RESC1005X04N 4546.6,2436.02 r0 top
R24 "MCR01MZPF4702" RESC1005X04N 4546.6,2495.08 r0 top
R25 "MCR01MZPF4702" RESC1005X04N 4795.28,2871.65 r270 top
R26 "MCR01MZPF4702" RESC1005X04N 4546.6,2554.13 r0 top
R27 "ERJ-2RKF1002X" RESC1005X04N 4546.6,2317.91 r0 top
R28 "ERJ-2RKF1002X" RESC1005X04N 4546.6,2259.84 r0 top
R29 "ERJ-2RKF1002X" RESC1005X04N 4755.91,2031.5 r0 top
R30 "ERJ-2RKF1002X" RESC1005X04N 4842.52,2031.5 r180 top
R31 "RC0603JR-070RL" RESC1608X06N 4787.4,1870.08 r90 top
R32 "RC0603JR-070RL" RESC1608X06N 4688.98,1870.08 r90 top
R33 "RC0603JR-070RL" RESC1608X06N 4738.19,1870.08 r90 top
R34 "ERJ-2RKF1002X" RESC1005X04N 5307.09,2035.43 r0 top
R35 "RC0402FR-07100KL" 0402_res 3059.06,1118.11 r90 top
R36 "ERJ-2RKF1503X" 0402_res 3059.06,1208.66 r90 top
R37 "ERJ-2RKF1002X" RESC1005X04N 5204.72,2031.5 r0 top
R39 "ERJ-2RKF1002X" RESC1005X04N 5051.18,2031.5 r0 top
R40 "ERJ-2RKF1002X" RESC1005X04N 4948.82,2031.5 r0 top
R41 "RC0603JR-070RL" RESC1608X06N 5161.42,1870.08 r270 top
R42 "RC0603JR-070RL" RESC1608X06N 5062.99,1870.08 r270 top
R43 "RC0603JR-070RL" RESC1608X06N 5112.2,1870.08 r270 top
R46 "RC0402FR-07220KL" RESC1005X04N 5655,2635 r270 top
R47 "RC0603JR-070RL" RESC1608X06N 4580.71,901.57 r90 top
R48 "RT0402BRD0710KL" RESC1005X04N 5435,1360 r0 top
R49 "RT0402BRD0710KL" RESC1005X04N 5433.07,1420.68 r180 top
R50 "MCR01MZPF4702" RESC1005X04N 5692.91,897.64 r180 top
R51 "MCR01MZPF1002" RESC1005X04N 5360.63,592.52 r180 top
R52 "RNCS0603BKE100R" RESC1608X06N 5535.43,562.99 r270 top
R53 "RC0603JR-070RL" RESC1608X06N 1604.33,907.48 r90 top
R54 "RC0603JR-070RL" RESC1608X06N 2423.23,1401.57 r90 top
R55 "RC0603JR-070RL" RESC1608X06N 1608.27,1860.24 r90 top
R56 "RC0603JR-070RL" RESC1608X06N 1608.27,1387.8 r90 top
R57 "RC0402FR-07330RL" 0402_res 2232.28,1594.49 r0 top
R58 "RC0402FR-071KL" 0402_res 2082.68,1594.49 r0 top
R59 "MCR01MZPF2200" 0402_res 1940.94,1590.55 r0 top
R60 "RC0603JR-070RL" RESC1608X06N 4423.23,1870.08 r270 top
R61 "RC0603JR-070RL" RESC1608X06N 3094.49,1870.08 r90 top
R62 "RC0603JR-070RL" RESC1608X06N 1940.94,1377.95 r180 top
R63 "RC0603JR-070RL" RESC1608X06N 2094.49,1377.95 r180 top
R64 "RC0603JR-070RL" RESC1608X06N 2244.09,1377.95 r180 top
R65 "ERJ-2RKF1002X" RESC1005X04N 1952.76,1334.65 r0 top
R66 "ERJ-2RKF1002X" RESC1005X04N 2104.72,1330.71 r0 top
R67 "ERJ-2RKF1002X" RESC1005X04N 2255.91,1326.77 r0 top
R68 "RC0402FR-07100KL" RESC1005X04N 79.29,2039.69 r270 top
R69 "MCR01MZPF5101" RESC1005X04N 815,3175 r90 top
R70 "MCR01MZPF5101" RESC1005X04N 815,3260 r270 top
R71 "RES0262" 0402_res 156.77,1823.15 r180 top
R72 "RES0263" 0402_res 81.26,1846.77 r270 top
R73 "RC0603JR-070RL" RESC1608X06N 615,2930 r180 top
R74 "RC0402FR-07100KL" RESC1005X04N 402.32,2032.99 r270 top
R75 "RC0402FR-07330RL" RESC1005X04N 740,2290 r0 top
R76 "RES0262" 0402_res 548.17,1826.23 r180 top
R77 "RES0263" 0402_res 399.49,1839.14 r270 top
R82 "ERJ-2RKF1002X" 0402_res 2937.01,1476.38 r270 top
R83 "RC0603JR-070RL" RESC1608X06N 590,2460 r0 top
R84 "MCR01MZPF1803" 0402_res 471.22,1826.23 r180 top
R85 "ERJ-2RKF1002X" 0402_res 2897.64,1476.38 r270 top
S1 "1825910-6" TL1105 3970.47,393.7 r180 top
S2 "1825910-6" TL1105 4954.72,403.54 r180 top
TP1 "TP-BLK" FP-5001-MFG 5539.37,1905.51 r0 top
TP2 "TP-BLK" FP-5001-MFG 1034,1448 r0 top
TP3 "TP-BLK" FP-5001-MFG 5051.18,572.68 r0 top
TP4 "TP-BLK" FP-5001-MFG 1208,1449 r0 top
U1 "IC FLASH 16MBIT SPI/QUAD 8USON" USON8P20X30X6 3275.59,925.2 r0 top
U2 "MM6108-MF08651-US" MF04 5059.06,2437.01 r180 top
U3 "IIS328DQTR" QFN50P400X400X185_HS-25N 2291.8,1005.79 r90 top
U4 "SHT40-AD1B-R3" DFN140P150X59-4N 2700.79,1488.19 r270 top
U5 "MIKROBUS HOST" MIKROBUS_Host_SD 3325.59,2869.58 r0 top locked
U6 "TPS63802DLAR" TPS63802DLAR 171.81,1976.69 r0 top
U7 "STLINK-V3MODS" STLINK-V3MODS 1174.57,3386.85 r0 top locked
U8 "TPS63802DLAR" TPS63802DLAR 490.91,1970 r0 top
VS1 "ESD5Z5.0T1G" SOD-523 464.95,3019.98 r180 top
X1 "ECS-300-10-37-CKM-TR" XTAL_SMD_2016 3274.61,1199.8 r0 top
X2 "ABS06-107-32.768KHZ-T" FP-ABS06-MFG 3204.72,1367.13 r90 top

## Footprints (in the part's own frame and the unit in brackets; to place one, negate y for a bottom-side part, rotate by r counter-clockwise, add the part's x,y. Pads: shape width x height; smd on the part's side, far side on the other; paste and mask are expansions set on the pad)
0201_DIODE [mm]
  rect 0.42x0.3 smd: A(0.31,0) K(-0.31,0)
  silkscreen extent -0.82,-0.33 -0.82,0.33
0402_cap [mil]
  rect 22x20 smd: 1(-17,0) 2(17,0)
0402_ind [mil]
  rect 22x20 smd: 1(-17,0) 2(17,0)
0402_res [mil]
  rect 22x20 smd: 1(-17,0) 2(17,0)
0603_cap [mm]
  rect 0.8x0.8 smd: 1(-0.8,0) 2(0.8,0)
0603_RES_AB_RA [mm]
  rrect50% 1x1 smd: A(-0.8,0) B(0.8,0) C(-0.8,1.6)
75915-308LF [mil] "CONN RCPT 8POS 0.1 GOLD PCB"
  rect 65x65 hole 35: 1(0,0)
  round 65 hole 35: 2(0,-100) 3(0,-200) 4(0,-300) 5(0,-400) 6(0,-500) 7(0,-600) 8(0,-700)
  silkscreen extent -50,-750 50,50
B2B-XH-A [mm] "JST 1x2 Header"
  rect 1.55x1.55 hole 1 paste+0 mask+0: 1(-1.25,0.525)
  round 1.55 hole 1 paste+0 mask+0: 2(1.25,0.525)
  silkscreen extent -3.7,-2.88 3.7,2.88
BLUENRGM2SP [mm]
  rect 1.2x1 smd: 1(-6.75,1.27) 2(-6.75,0) 3(-6.75,-1.27) 4(-6.75,-2.54) 5(-6.75,-3.81) 15(6.75,-3.81) 16(6.75,-2.54) 17(6.75,-1.27) 18(6.75,0) 19(6.75,1.27) 20(6.75,2.54)
  rect 1x1.2 smd: 6(-5.29,-4.81) 7(-4.02,-4.81) 8(-2.75,-4.81) 9(-1.48,-4.81) 10(-0.21,-4.81) 11(1.06,-4.81) 12(2.33,-4.81) 13(3.6,-4.81) 14(4.87,-4.81)
  silkscreen extent -8,1.17 6.75,6.69
CAPC0603X03N [mm] "Chip Capacitor, 2-Leads, Body 0.60x0.30mm, IPC Medium Density"
  rect 0.5x0.42 smd: 1(-0.31,0) 2(0.31,0)
CAPC1005X06N [mm] "Chip Capacitor, 2-Leads, Body 1.00x0.50mm, IPC Medium Density"
  rect 0.66x0.62 smd: 1(-0.44,0) 2(0.44,0)
CAPC1608X06N [mm] "Chip Capacitor, 2-Leads, Body 1.60x0.80mm, IPC Medium Density"
  rect 0.95x0.95 smd: 1(-0.75,0) 2(0.75,0)
CAPC3225X20N [mm] "Chip Capacitor, 2-Leads, Body 3.20x2.50mm, IPC Medium Density"
  rect 1.55x2.7 smd: 1(-1.325,0) 2(1.325,0)
  silkscreen extent -0.15,-1.25 0.15,1.25
DFN140P150X59-4N [mm] "DFN, 4-Leads, Body 1.50x1.50mm, Pitch 1.40mm, IPC Medium Density"
  rect 0.5x0.3 smd: 1(-0.7,0.4) 2(-0.7,-0.4) 3(0.7,-0.4) 4(0.7,0.4)
  silkscreen extent -1.35,-0.8 0.8,0.8
FIDUCIAL_1MM [mm]
  round 1 smd paste-1 mask+0: 1(0,0)
FP-5001-MFG [mm]
  round 1.57 hole 1.016 paste+0 mask+0: 1(0,0)
  silkscreen extent -1.35,-1.34 1.35,1.34
FP-ABS06-MFG [mm]
  rect 0.75x1.4 smd paste+0 mask+0: 1(-0.725,0) 2(0.725,0)
  silkscreen extent -1.07,-1.07 1.07,1.07
FP-QPC02SXGN-RC-MFG [mil]
FP-SOT23-IPC_A [mm]
  rect 1.874x0.612 smd paste+0 mask+0: 1(-0.935,0.95)
  rrect100% 1.874x0.612 smd paste+0 mask+0: 2(-0.935,-0.95) 3(0.935,0)
  silkscreen extent 0.38,-1.46 0.65,1.46
FTSH_108_D_K [mil]
  rect 40x40 hole 23.62: 1(-175,-25)
  round 40 hole 23.62: 2(-175,25) 3(-125,-25) 4(-125,25) 5(-75,-25) 6(-75,25) 7(-25,-25) 8(-25,25) 9(25,-25) 10(25,25) 11(75,-25) 12(75,25) 13(125,-25) 14(125,25) 15(175,-25) 16(175,25)
  silkscreen extent -210,-110 210,110
HDR1X2 [mm] "Connector; Header; 2 Position"
  rect 1.5x1.8 hole 0.9: 1(-1.27,0)
  oval 1.5x1.8 hole 0.9: 2(1.27,0)
  silkscreen extent -2.54,-1.27 2.54,1.27
HDR1X3 [mm] "Connector; Header; 3 Position"
  rect 1.5x1.5 hole 0.9: 1(-2.54,0)
  round 1.5 hole 0.9: 2(0,0) 3(2.54,0)
  silkscreen extent -3.81,-1.27 3.81,1.27
"HDR1X4 - Short Gold" [mm] "Connector; Header; 4 Position, 1x4"
  rect 1.5x1.5 hole 0.9: 1(-3.81,0)
  round 1.5 hole 0.9: 2(-1.27,0) 3(1.27,0) 4(3.81,0)
  silkscreen extent -5.08,-1.27 5.08,1.27
"HDR1X5 - Short Gold" [mm] "Connector; Header; 5 Position, 1x5"
  rect 1.5x1.5 hole 0.9: 1(-3.81,0)
  round 1.5 hole 0.9: 2(-1.27,0) 3(1.27,0) 4(3.81,0) 5(6.35,0)
  silkscreen extent -5.08,-1.3 7.68,1.3
"HDR2X8 Short Gold" [mm] "Connector; Header; 8x2 Position, 2x8"
  rect 1.5x1.8 hole 0.9: 1(-7.62,-1.27)
  oval 1.5x1.8 hole 0.9: 2(-7.62,1.27) 3(-5.08,-1.27) 4(-5.08,1.27) 5(-2.54,-1.27) 6(-2.54,1.27) 7(0,-1.27) 8(0,1.27) 9(2.54,-1.27) 10(2.54,1.27) 11(5.08,-1.27) 12(5.08,1.27) 13(7.62,-1.27) 14(7.62,1.27) 15(10.16,-1.27) 16(10.16,1.27)
  silkscreen extent -8.89,-2.54 11.43,2.54
"HDR2X9 Female" [mm] "Connector; Header; 9x2 Position, Female"
  rect 1.5x1.8 hole 0.9: 1(0,0)
  oval 1.5x1.8 hole 0.9: 2(0,2.54) 3(2.54,0) 4(2.54,2.54) 5(5.08,0) 6(5.08,2.54) 7(7.62,0) 8(7.62,2.54) 9(10.16,0) 10(10.16,2.54) 11(12.7,0) 12(12.7,2.54) 13(15.24,0) 14(15.24,2.54) 15(17.78,0) 16(17.78,2.54) 17(20.32,0) 18(20.32,2.54)
  silkscreen extent -1.27,-1.27 21.59,3.81
INDC1608X10N [mm] "Chip Inductor, 2-Leads, Body 1.60x0.80mm, IPC Medium Density"
  rect 0.93x1.02 smd: 1(-0.785,0) 2(0.785,0)
INDC2520X120N [mm]
  rect 1.24x2.22 smd: 1(-1.09,0) 2(1.09,0)
  silkscreen extent -0.15,-1.1 0.15,1.1
LED_0805_BLUE [mm]
  rect 1.2x1.2 smd: A(-1,0) K(1,0)
  silkscreen extent -1.83,-0.83 2.25,0.82
LED_0805_GREEN [mm]
  rect 1.2x1.2 smd: A(-1,0) K(1,0)
  silkscreen extent -1.83,-0.82 2.25,0.82
LED_0805_RED [mm]
  rect 1.2x1.2 smd: A(-1,0) K(1,0)
  silkscreen extent -1.83,-0.82 2.25,0.82
MF04 [mm]
  rect 2x2 smd: 1(-8.9,6.65) 12(8.9,6.65) 20(8.9,-6.65) 31(-8.9,-6.65)
  rect 1x2 smd: 2(-6.75,6.65) 3(-5.25,6.65) 4(-3.75,6.65) 5(-2.25,6.65) 6(-0.75,6.65) 7(0.75,6.65) 8(2.25,6.65) 9(3.75,6.65) 10(5.25,6.65) 11(6.75,6.65) 21(6.75,-6.65) 22(5.25,-6.65) 23(3.75,-6.65) 24(2.25,-6.65) 25(0.75,-6.65) 26(-0.75,-6.65) 27(-2.25,-6.65) 28(-3.75,-6.65) 29(-5.25,-6.65) 30(-6.75,-6.65)
  rect 2x1 smd: 13(8.9,4.5) 14(8.9,3) 15(8.9,1.5) 16(8.9,0) 17(8.9,-1.5) 18(8.9,-3) 19(8.9,-4.5) 32(-8.9,-4.5) 33(-8.9,-3) 34(-8.9,-1.5) 35(-8.9,0) 36(-8.9,1.5) 37(-8.9,3) 38(-8.9,4.5)
  silkscreen extent -10.15,-7.9 10.15,8.9
MH_300_275_NPTH [mm] "Non-plated mount hole M2.5 3.00mm diameter"
  round 2.75 hole 2.75 unplated mask+0: 1(0,0)
  Keep-Out Layer circle w0.2: c0,0 r1.65
MIKROBUS_Host_SD [mil] "MIKROBUS HOST SOCKET"
  silkscreen extent -100,-900 1000,225
QFN50P400X400X185_HS-25N [mm] "QFN, 24-Leads, Body 4.00x4.00mm, Pitch 0.50mm, Thermal Pad 2.35x2.35mm, IPC Medium Density"
  oval 0.85x0.35 smd paste-0.05 mask+0: 1(-1.9,1.25) 2(-1.9,0.75) 3(-1.9,0.25) 4(-1.9,-0.25) 5(-1.9,-0.75) 6(-1.9,-1.25) 13(1.9,-1.25) 14(1.9,-0.75) 15(1.9,-0.25) 16(1.9,0.25) 17(1.9,0.75)
  oval 0.35x0.85 smd paste-0.05 mask+0: 7(-1.25,-1.9) 8(-0.75,-1.9) 9(-0.25,-1.9) 10(0.25,-1.9) 11(0.75,-1.9) 12(1.25,-1.9) 19(1.25,1.9) 20(0.75,1.9) 21(0.25,1.9) 22(-0.25,1.9) 23(-0.75,1.9) 24(-1.25,1.9)
  oval 0.8x0.3 smd paste-0.05 mask+0: 18(1.9,1.25)
  rect 2.35x2.35 smd paste-0.05 mask+0: 25(0,0)
  silkscreen extent -2.92,-2.15 2.15,2.15
RESC1005X04N [mm] "Chip Resistor, 2-Leads, Body 1.00x0.50mm, IPC Medium Density"
  rect 0.66x0.62 smd: 1(-0.44,0) 2(0.44,0)
RESC1608X06N [mm] "Chip Resistor, 2-Leads, Body 1.55x0.80mm, IPC Medium Density"
  rect 0.95x0.95 smd: 1(-0.75,0) 2(0.75,0)
SCREW_TERM_2WAY_5MM [mm]
  round 2.2 hole 1.5: 1(0,0) 2(5,0)
  silkscreen extent -3.1,-3.8 8.13,4.2
SM04B-SRSS-TB [mm]
  rect 1.55x0.6 smd mask+0: 1(-1.937,1.5) 2(-1.937,0.5) 3(-1.937,-0.5) 4(-1.937,-1.5)
  rect 1.8x1.2 smd mask+0: 5(1.937,-2.8) 6(1.937,2.8)
  silkscreen extent -2.54,-3 2.41,3
SM2924-Footprint-1 [mm] "Footprint and 3D model for SM2924 component"
  rect 3.12x1 smd: 1(7.29,0)
  rect 2.54x2.47 smd: 2(7.001,-3.238) 2(7.001,3.239)
  Top Layer region: 7.254,-5.235 7.254,-4.727 5.791,-4.727 5.791,-5.235
  Top Layer region: 4.595,-6.719 5.103,-6.719 5.103,-5.256 4.595,-5.256
  Top Layer region: 5.611,-6.719 6.119,-6.719 6.119,-5.256 5.611,-5.256
  Top Layer region: 3.579,-6.719 4.087,-6.719 4.087,-5.256 3.579,-5.256
  Top Layer region: 2.563,-6.719 3.071,-6.719 3.071,-5.256 2.563,-5.256
  Top Layer region: 1.547,-6.719 2.055,-6.719 2.055,-5.256 1.547,-5.256
  Top Layer region: 0.531,-6.719 1.039,-6.719 1.039,-5.256 0.531,-5.256
  Top Layer region: -0.485,-6.719 0.023,-6.719 0.023,-5.256 -0.485,-5.256
  Top Layer region: -0.485,5.256 0.023,5.256 0.023,6.719 -0.485,6.719
  Top Layer region: 0.531,5.256 1.039,5.256 1.039,6.719 0.531,6.719
  Top Layer region: 1.547,5.256 2.055,5.256 2.055,6.719 1.547,6.719
  Top Layer region: 2.563,5.256 3.071,5.256 3.071,6.719 2.563,6.719
  Top Layer region: 3.579,5.256 4.087,5.256 4.087,6.719 3.579,6.719
  Top Layer region: 5.611,5.256 6.119,5.256 6.119,6.719 5.611,6.719
  Top Layer region: 4.595,5.256 5.103,5.256 5.103,6.719 4.595,6.719
  Top Layer region: 8.718,-2.404 8.718,-2.2 7.255,-2.2 7.255,-2.404
  Top Layer region: 7.763,-4.956 8.271,-4.956 8.271,-3.492 7.763,-3.492
  Top Layer region: 7.255,-2.912 7.255,-3.42 8.718,-3.42 8.718,-2.912
  Top Layer region: 6.747,-4.956 7.255,-4.956 7.255,-3.492 6.747,-3.492
  Top Layer region: 7.255,-3.928 7.255,-4.436 8.718,-4.436 8.718,-3.928
  Top Layer region: 8.718,3.928 8.718,4.436 7.255,4.436 7.255,3.928
  Top Layer region: 6.747,3.493 7.255,3.493 7.255,4.956 6.747,4.956
  Top Layer region: 8.718,2.912 8.718,3.42 7.255,3.42 7.255,2.912
  Top Layer region: 7.763,3.493 8.271,3.493 8.271,4.956 7.763,4.956
  Top Layer region: 7.255,2.404 7.255,2.2 8.718,2.2 8.718,2.404
  Top Layer region: 5.791,5.235 5.791,4.727 7.254,4.727 7.254,5.235
  Top Layer keep-out lines w0: 8.977,2 8.977,0.627 5.73,0.627 5.73,2 8.977,2 ; 8.977,-0.627 5.73,-0.627 5.73,-2 8.977,-2 8.977,-0.627
  Keep-Out Layer lines w0.013: -1.131,3.565 4.35,3.565 cw(c4.85,3.565) 5.35,3.565 5.35,-3.565 cw(c4.85,-3.565) 4.35,-3.565 -1.131,-3.565
  silkscreen extent 6.45,-5 7.35,5
SOD-123FL [mm] "Surface Mount Schottky Diode"
  rect 0.91x1.22 smd: A(1.64,0) K(-1.64,0)
  silkscreen extent -1.35,-0.82 1.35,0.82
SOD-523 [mm]
  rect 0.5x0.4 smd: A(0.65,0) K(-0.65,0)
  silkscreen extent -1.2,-0.38 0.4,0.4
SOD-523-DIODE [mm]
  rect 0.5x0.4 smd: A(0.65,0) K(-0.65,0)
  silkscreen extent -0.4,-0.38 0.4,0.4
SOT95P240X120_GSD-3N(SOT23-3L) [mm] "SOT23, 3-Leads, Body 2.90x2.35mm, Pitch 0.95mm, IPC High Density"
  rrect50% 1x1.4 smd: D(0,1.019) G(-0.95,-1.1) S(0.95,-1.1)
  silkscreen extent -1.56,-0.2 1.56,0.75
STLINK-V3MODS [mil]
  rect 74.8x42.13 smd paste+0 mask+0: 1(-288.19,-390) 2(-288.19,-440) 3(-288.19,-490) 4(-288.19,-540) 5(-288.19,-590) 6(-288.19,-640) 7(-288.19,-690) 8(-288.19,-740) 9(-288.19,-790) 10(-288.19,-840) 11(-288.19,-890) 12(-288.19,-940) 13(-288.19,-990) 14(-288.19,-1040) 15(-288.19,-1090) 16(-288.19,-1140) 17(288.19,-1140) 18(288.19,-1090) 19(288.19,-1040) 20(288.19,-990) 21(288.19,-940) 22(288.19,-890) 23(288.19,-840) 24(288.19,-790) 25(288.19,-740) 26(288.19,-690) 27(288.19,-640) 28(288.19,-590) 29(288.19,-540) 30(288.19,-490) 31(288.19,-440) 32(288.19,-390)
  silkscreen extent -300,-1180 300,0
STM32U585VIT6 [mm]
  rect 1.475x0.3 smd: 1(-7.738,6) 2(-7.738,5.5) 3(-7.738,5) 4(-7.738,4.5) 5(-7.738,4) 6(-7.738,3.5) 7(-7.738,3) 8(-7.738,2.5) 9(-7.738,2) 10(-7.738,1.5) 11(-7.738,1) 12(-7.738,0.5) 13(-7.738,0) 14(-7.738,-0.5) 15(-7.738,-1) 16(-7.738,-1.5) 17(-7.738,-2) 18(-7.738,-2.5) 19(-7.738,-3) 20(-7.738,-3.5) 21(-7.738,-4) 22(-7.738,-4.5) 23(-7.738,-5) 24(-7.738,-5.5) 25(-7.738,-6) 51(7.738,-6) 52(7.738,-5.5) 53(7.738,-5) 54(7.738,-4.5) 55(7.738,-4) 56(7.738,-3.5) 57(7.738,-3) 58(7.738,-2.5) 59(7.738,-2) 60(7.738,-1.5) 61(7.738,-1) 62(7.738,-0.5) 63(7.738,0) 64(7.738,0.5) 65(7.738,1) 66(7.738,1.5) 67(7.738,2) 68(7.738,2.5) 69(7.738,3) 70(7.738,3.5) 71(7.738,4) 72(7.738,4.5) 73(7.738,5) 74(7.738,5.5) 75(7.738,6)
  rect 0.3x1.475 smd: 26(-6,-7.738) 27(-5.5,-7.738) 28(-5,-7.738) 29(-4.5,-7.738) 30(-4,-7.738) 31(-3.5,-7.738) 32(-3,-7.738) 33(-2.5,-7.738) 34(-2,-7.738) 35(-1.5,-7.738) 36(-1,-7.738) 37(-0.5,-7.738) 38(0,-7.738) 39(0.5,-7.738) 40(1,-7.738) 41(1.5,-7.738) 42(2,-7.738) 43(2.5,-7.738) 44(3,-7.738) 45(3.5,-7.738) 46(4,-7.738) 47(4.5,-7.738) 48(5,-7.738) 49(5.5,-7.738) 50(6,-7.738) 76(6,7.738) 77(5.5,7.738) 78(5,7.738) 79(4.5,7.738) 80(4,7.738) 81(3.5,7.738) 82(3,7.738) 83(2.5,7.738) 84(2,7.738) 85(1.5,7.738) 86(1,7.738) 87(0.5,7.738) 88(0,7.738) 89(-0.5,7.738) 90(-1,7.738) 91(-1.5,7.738) 92(-2,7.738) 93(-2.5,7.738) 94(-3,7.738) 95(-3.5,7.738) 96(-4,7.738) 97(-4.5,7.738) 98(-5,7.738) 99(-5.5,7.738) 100(-6,7.738)
  silkscreen extent -8.35,-6.65 6.65,6.87
TL1105 [mm]
  round 1.6 hole 1: 1(0,0) 2(6.5,0) 3(6.5,4.5) 4(0,4.5)
  silkscreen extent 0.25,-0.75 6.25,5.25
TPS63802DLAR [mm]
  rect 0.6x0.25 smd paste+0 mask+0: 1(-0.9,1) 2(-0.9,0.5) 3(-0.9,0) 4(-0.9,-0.5) 5(-0.9,-1)
  rect 0.9x0.25 smd paste+0 mask+0: 6(0.75,-1) 7(0.75,-0.5) 9(0.75,0.5) 10(0.75,1)
  rect 1.3x0.25 smd paste-0.637 mask+0: 8(0.55,0)
  silkscreen extent -1,-1.65 1,1.65
U_FL-R-SMT [mm]
  rrect50% 1x1 smd: 1(0,-1.5)
  rect 1.05x2.2 smd: 2(-1.475,0) 3(1.475,0)
  Top Layer keep-out region: -1.5,-1.55 1.5,-1.55 1.5,1.55 -1.5,1.55
  silkscreen extent -1.55,-1.52 1.55,1.5
USB-C_RCP [mm] "CONN RCP USB3.1 TYPEC 24P SMD RA"
  rect 0.28x0.7 smd mask+0: A1(-3,3.085) A2(-2.5,3.085) A3(-2,3.085) A4(-1.5,3.085) A5(-1,3.085) A6(-0.5,3.085) A7(0.5,3.085) A8(1,3.085) A9(1.5,3.085) A10(2,3.085) A11(2.5,3.085) A12(3,3.085) B2(2.25,1.385) B3(1.75,1.385) B4(1.25,1.385) B5(0.75,1.385) B6(0.25,1.385) B7(-0.25,1.385) B8(-0.75,1.385) B9(-1.25,1.385) B10(-1.75,1.385) B11(-2.25,1.385)
  rect 0.88x0.7 smd mask+0: B1(3.05,1.385) B12(-3.05,1.385)
  oval 1.1x2.1 hole 0.6 slot 1.6 at 90 deg: SH1(-4.32,2.275) SH2(4.32,2.275)
  oval 1.1x3.6 hole 0.6 slot 2.1 at 90 deg copper offset 0,0.5: SH3(4.62,-3.085) SH4(-4.62,-3.085)
  silkscreen extent -3.76,3.65 -3.51,3.9
USON8P20X30X6 [mm] "8-Pad USON 2x3x0.6mm"
  rect 0.8x0.25 smd: 1(-1.345,0.75) 2(-1.345,0.25) 3(-1.345,-0.25) 4(-1.345,-0.75) 5(1.345,-0.75) 6(1.345,-0.25) 7(1.345,0.25) 8(1.345,0.75)
  rect 0.2x1.6 smd: 9(0,0)
  silkscreen extent -1.9,1.19 -1.8,1.29
WL-SFCW_1206 [mm] "SMT Full-color Chip LED Waterclear, body 3.2x1.6mm"
  rect 1.6x1.2 smd: 1(-1.5,0.8) 2(-1.5,-0.8) 3(1.5,-0.8) 4(1.5,0.8)
  silkscreen extent -2.92,-0.79 0.41,0.81
XTAL_SMD_2016 [mm] "XTAL 4-pin SMD 2016"
  rect 0.85x0.75 smd mask+0: 1(-0.675,-0.525) 2(0.675,-0.525) 3(0.675,0.525) 4(-0.675,0.525)
  silkscreen extent -1.5,-1.1 -1.3,-0.9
